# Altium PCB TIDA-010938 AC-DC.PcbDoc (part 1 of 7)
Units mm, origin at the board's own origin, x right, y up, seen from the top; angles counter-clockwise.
Board outline 275 x 170 mm, 4 copper layers (Top Layer, Layer 1, Layer 2, Bottom Layer), stack 1.787 mm thick; 711 components, 426 nets, 2196 pads, 1444 vias.
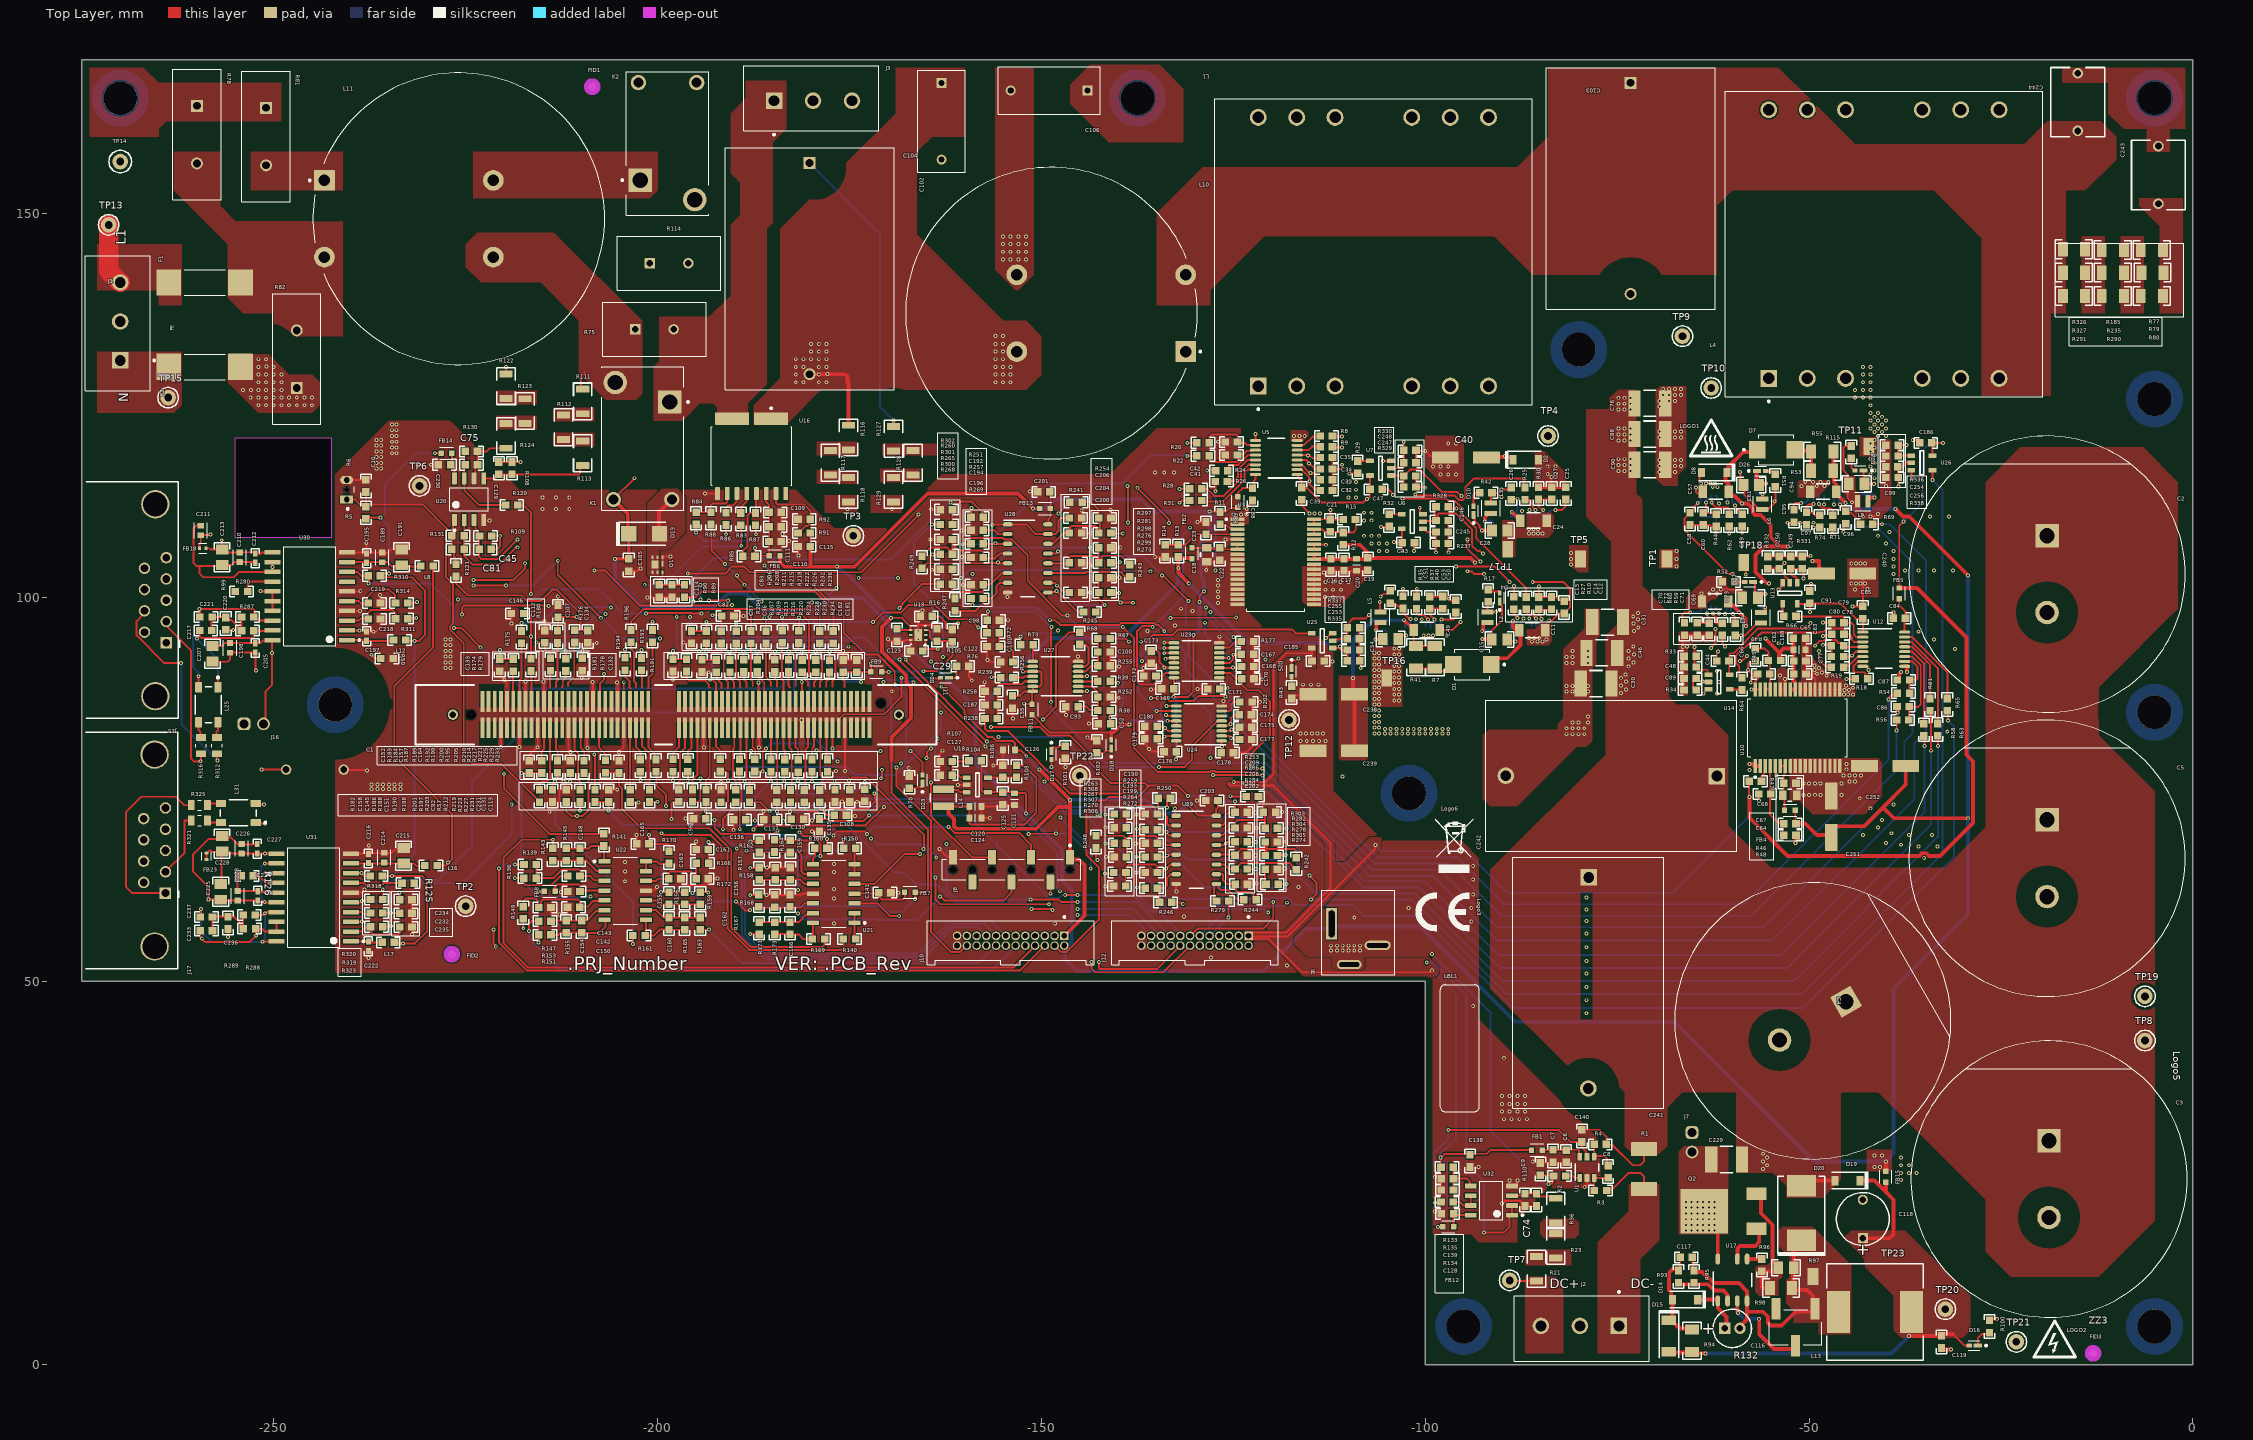
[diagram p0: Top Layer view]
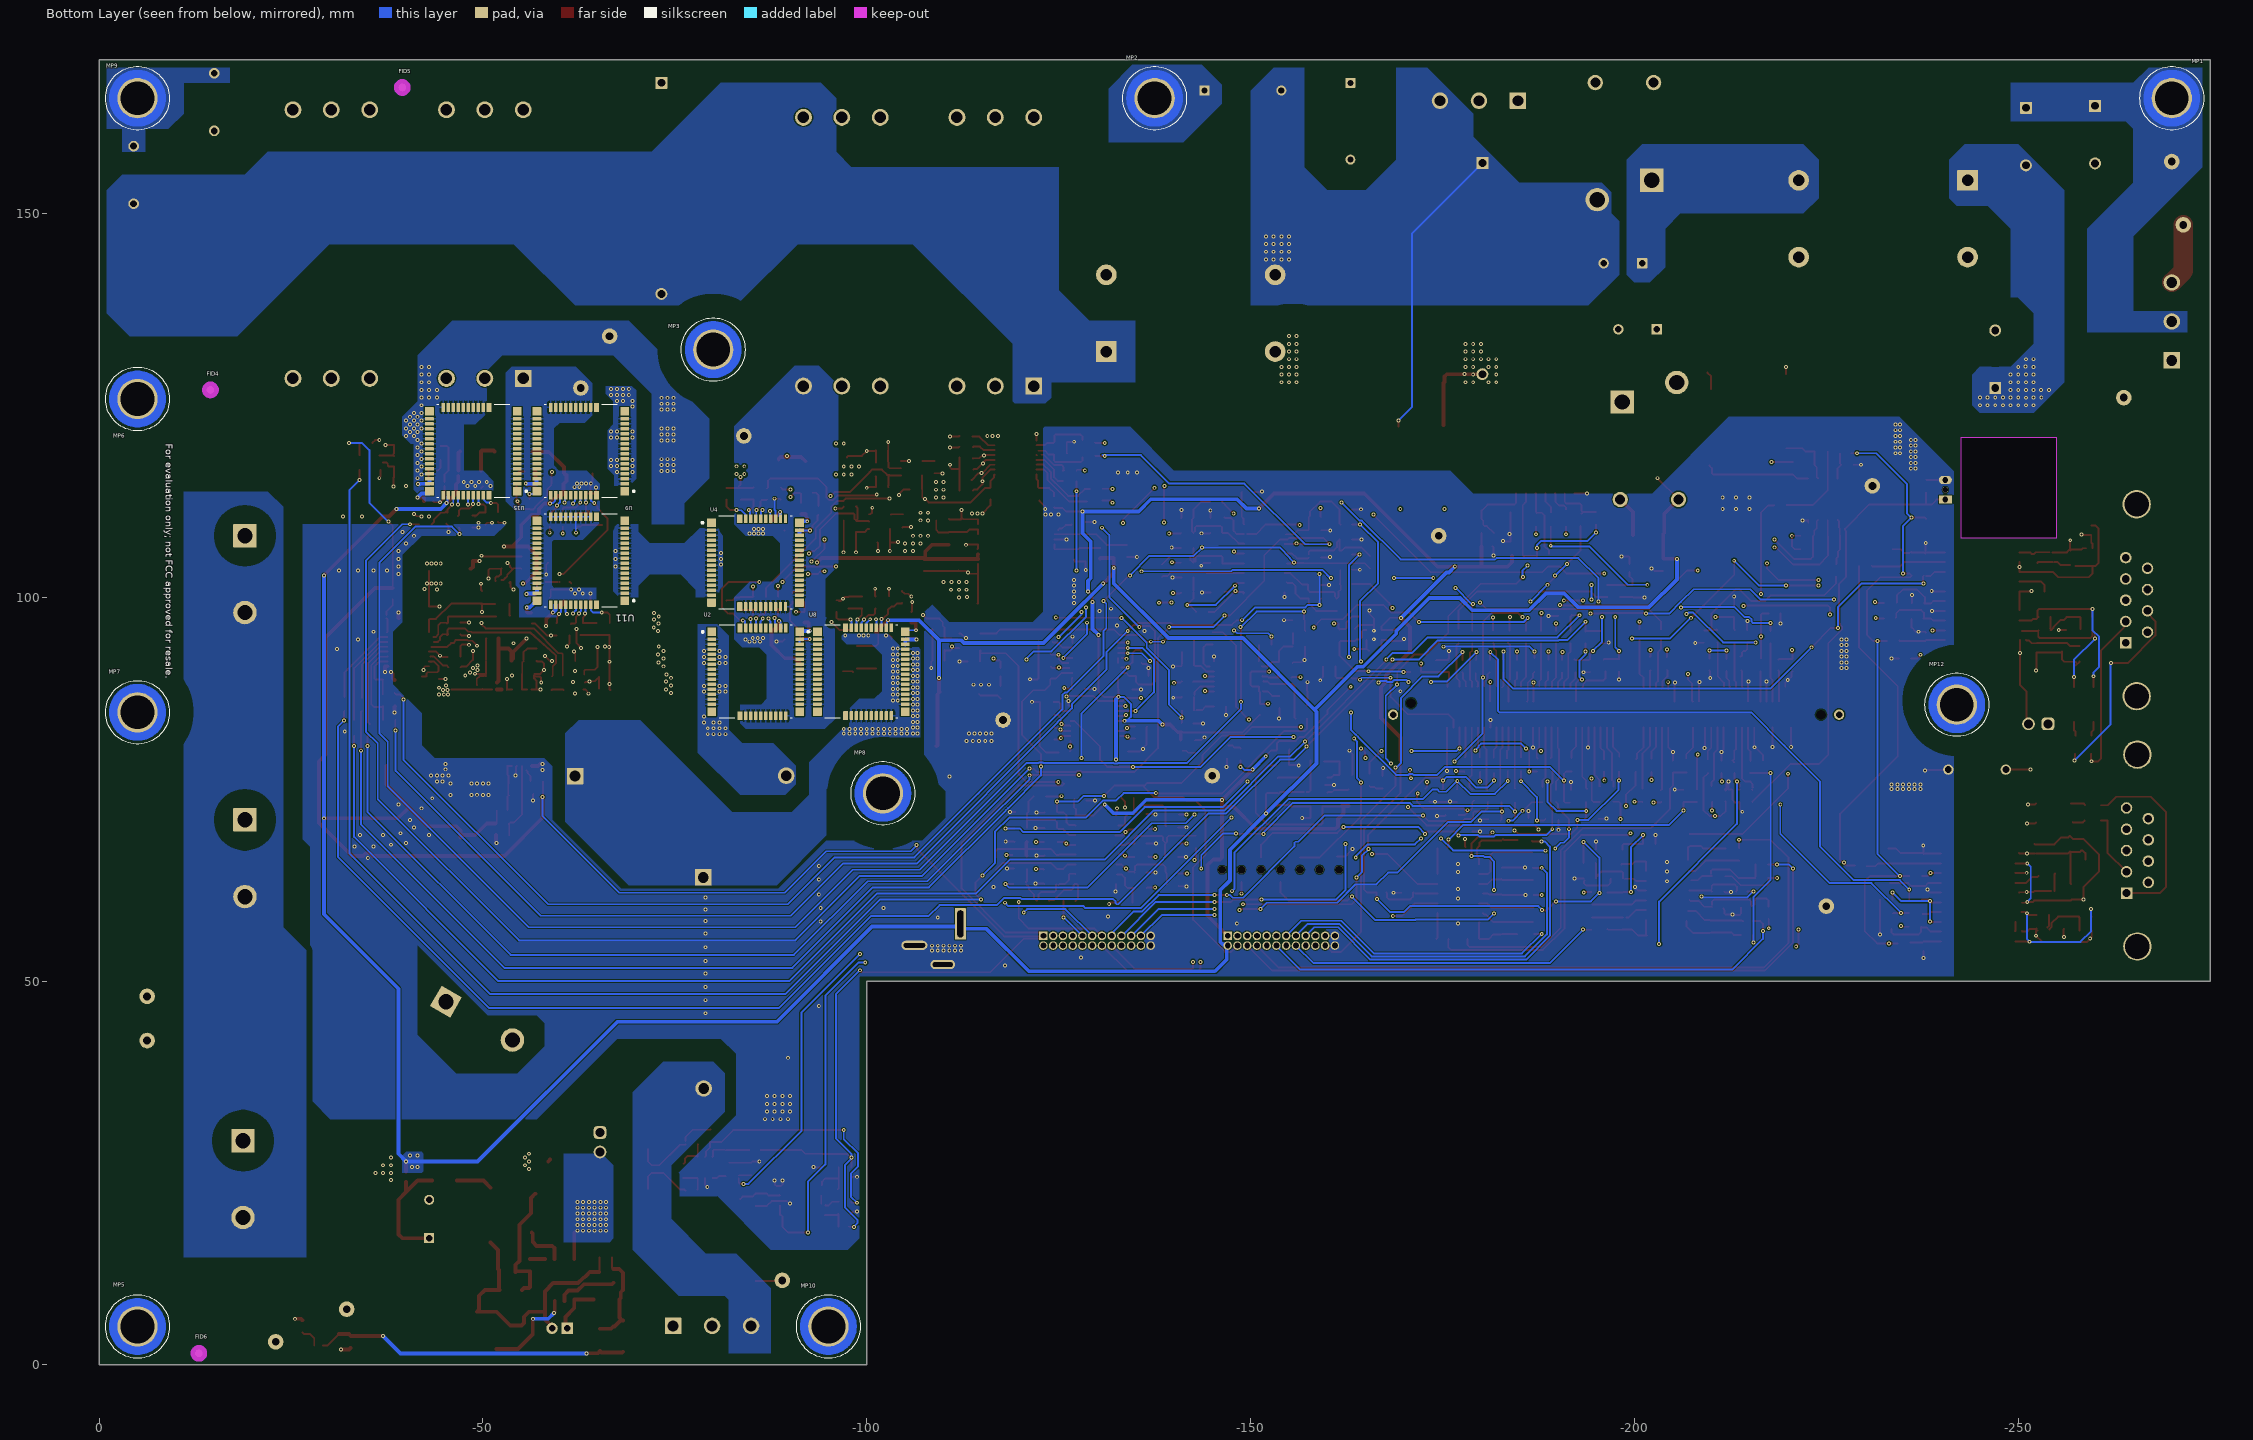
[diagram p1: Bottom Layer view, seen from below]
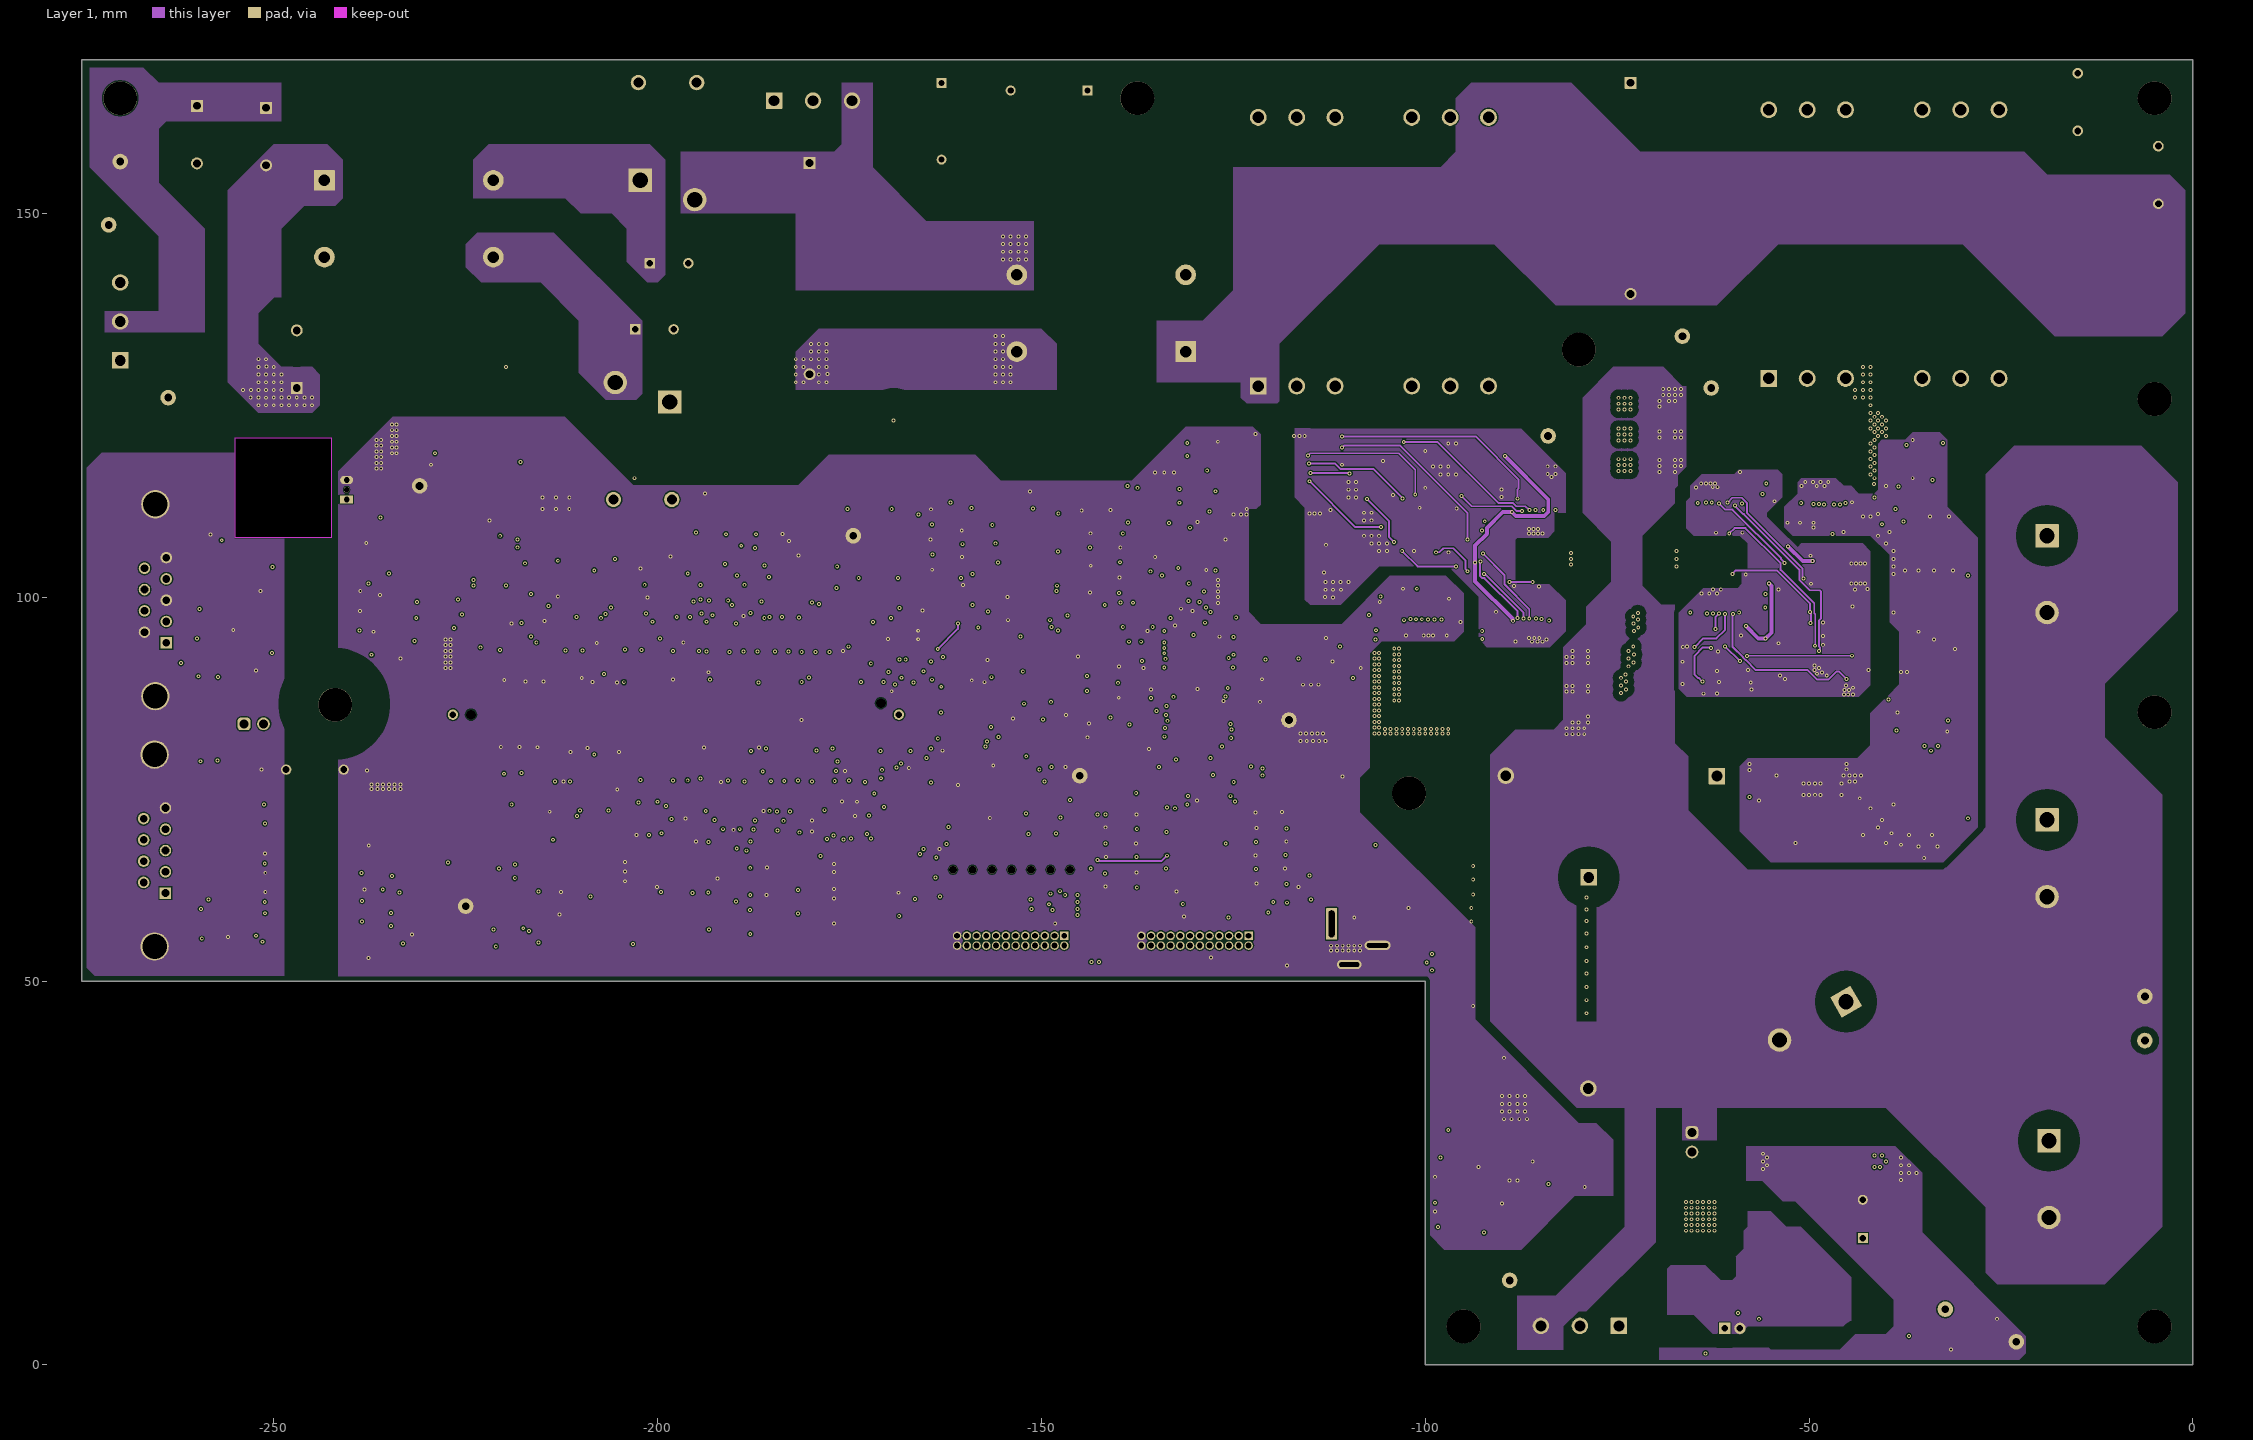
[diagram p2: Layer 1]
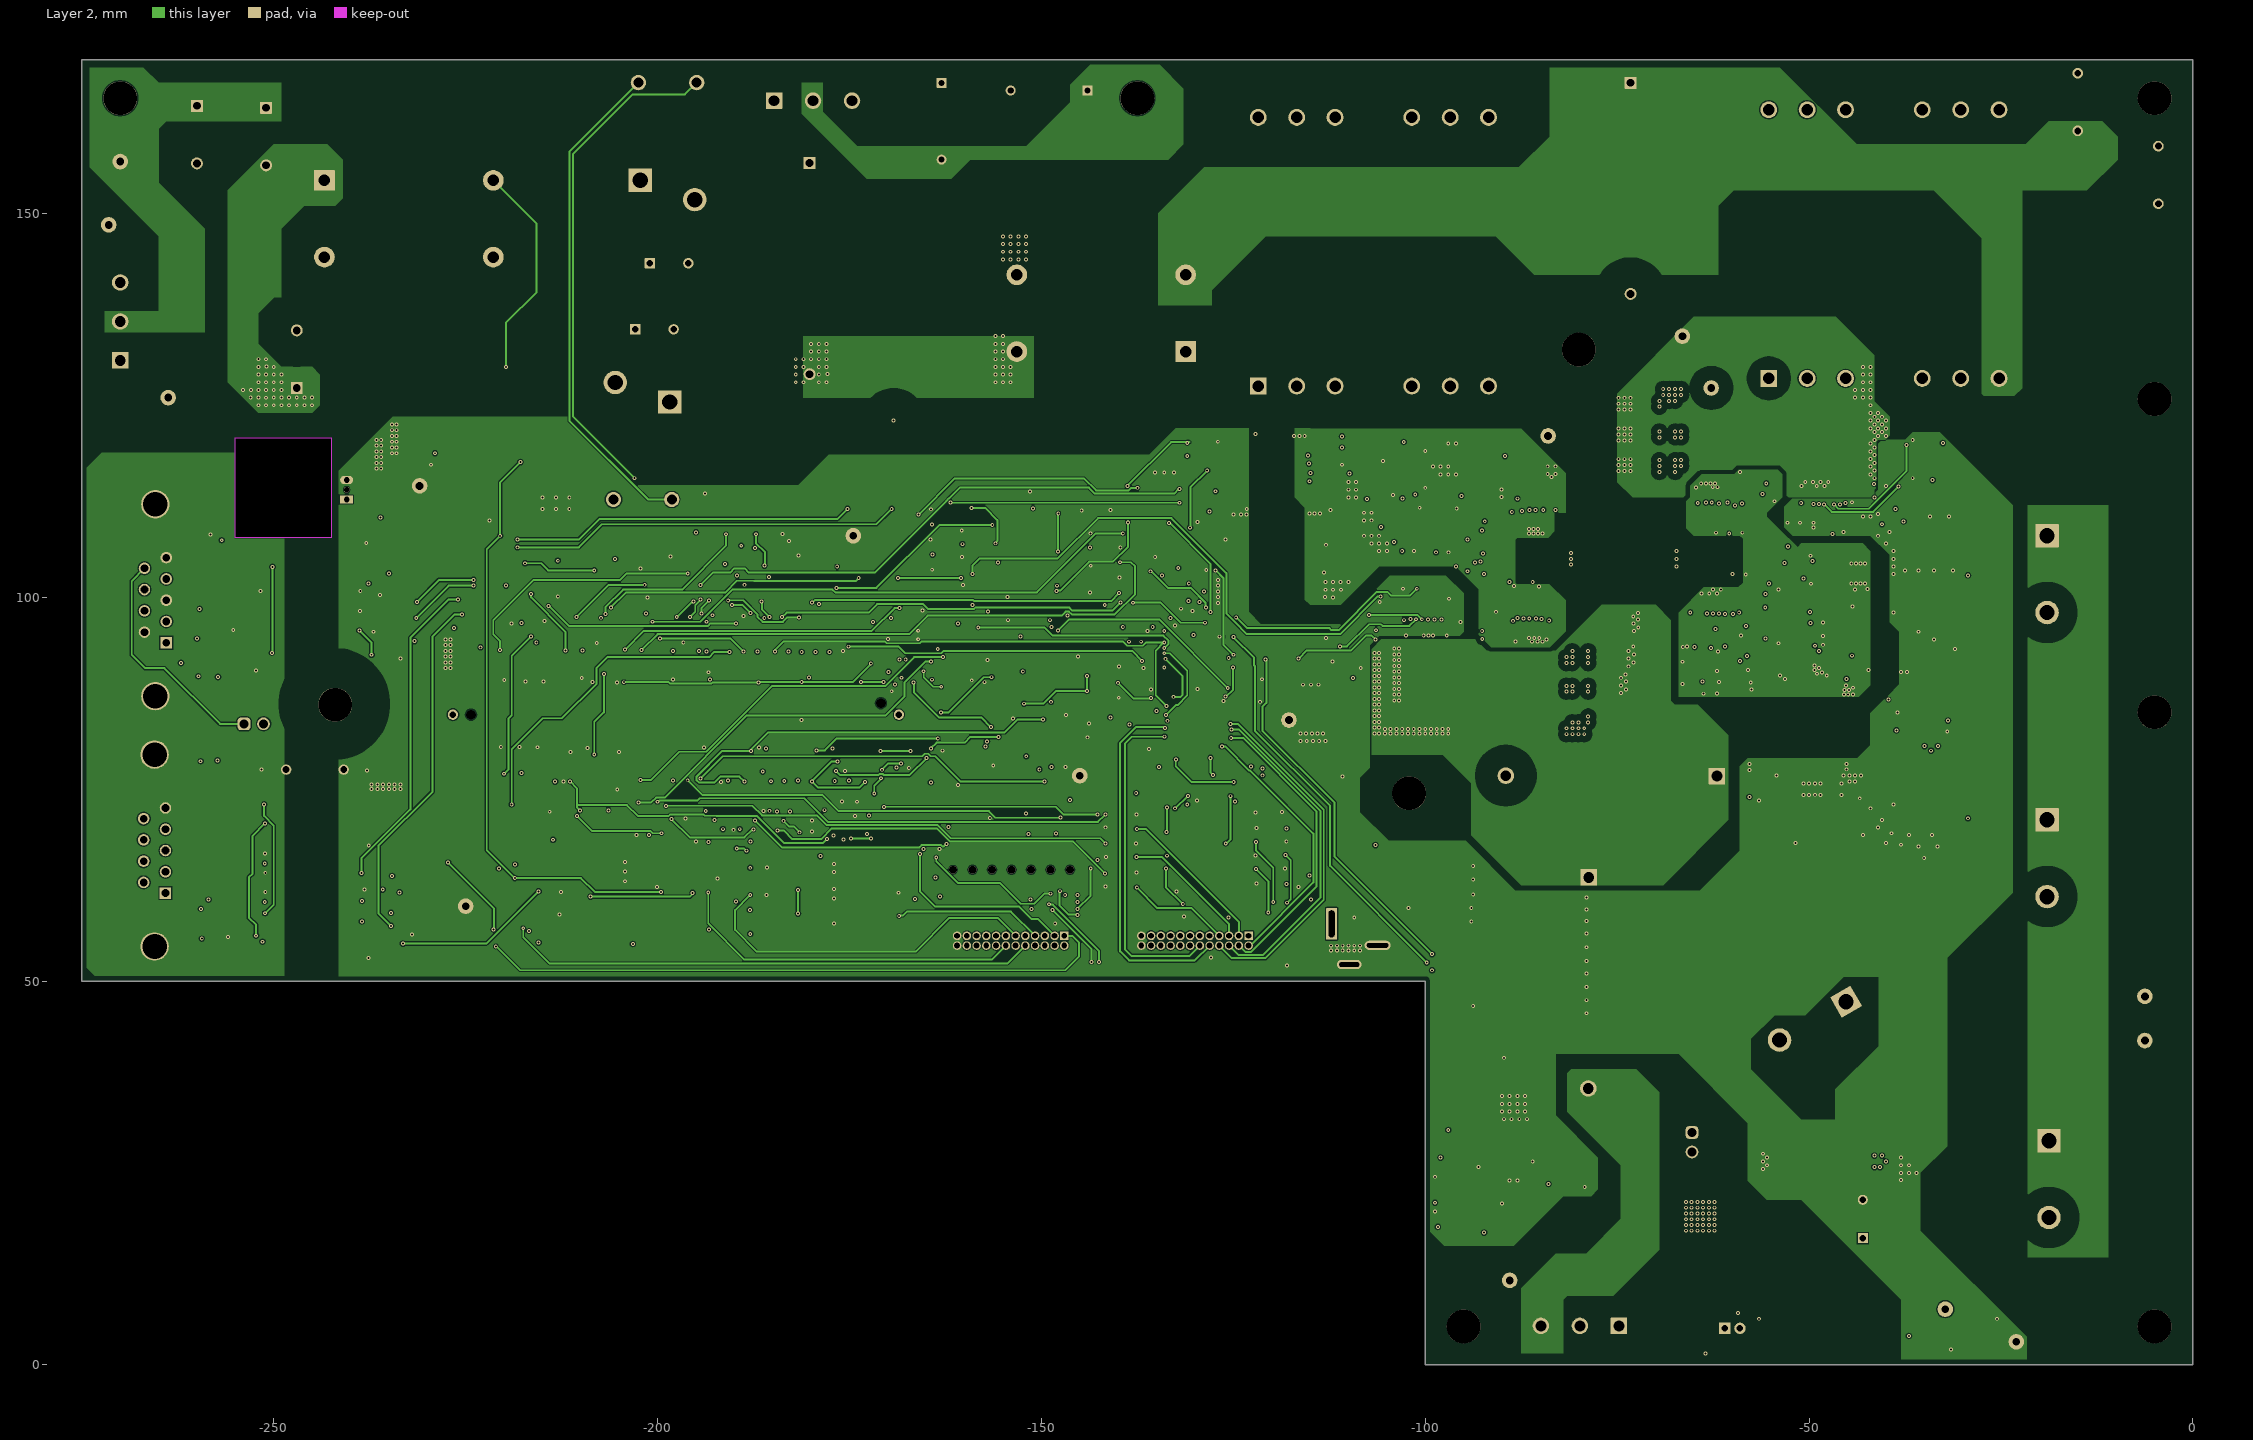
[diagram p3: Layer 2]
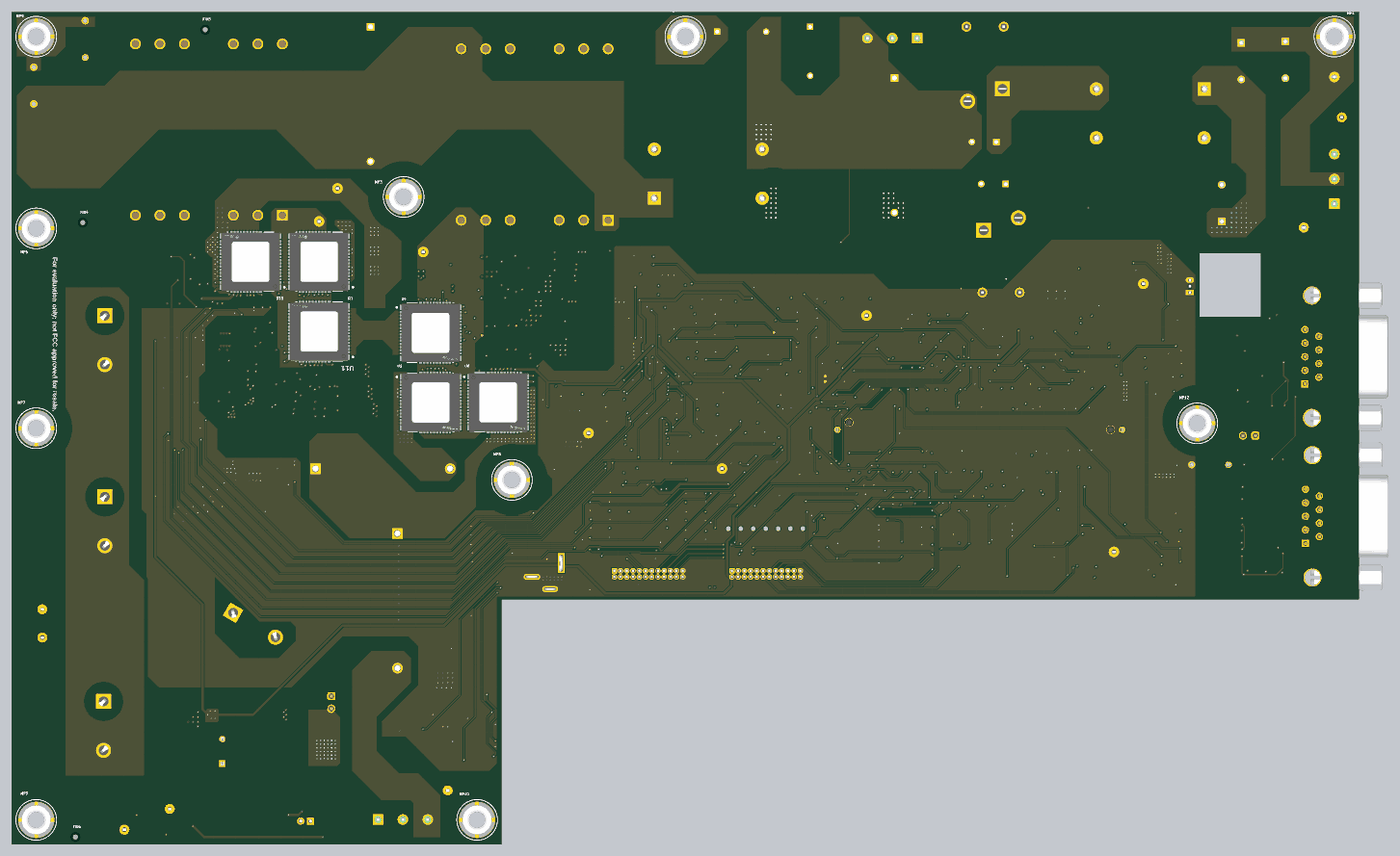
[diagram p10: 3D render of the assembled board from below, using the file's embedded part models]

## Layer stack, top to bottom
Top Solder: solder mask 0.0102, Solder Resist, Dk 3.5
Top Layer: signal copper 0.0356
Dielectric 1: prepreg 0.0711, PP-006, Dk 4.1
Layer 1: signal copper 0.035
Dielectric1: core 1.5037, FR-4 High Tg, Dk 4.8
Layer 2: signal copper 0.035
Dielectric 2: prepreg 0.0711, PP-006, Dk 4.1
Bottom Layer: signal copper 0.0356
Bottom Solder: solder mask 0.0102, Solder Resist, Dk 3.5

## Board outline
-100,0 0,0 0,170 -275,170 -275,50 -100,50
cut-out: -242.5,120.75 -242.5,107.75 -255,107.75 -255,120.75

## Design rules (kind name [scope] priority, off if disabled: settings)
AcuteAngle [All] p1: minimum=4.50000000000000E+0001 checktracksonly=FALSE
AssemblyTestPointUsage [All] p1: valid=2
BoardOutlineClearance BoardOutlineClearance_MountingHoles [OnCopper and InComponentClass('Mounting Holes')] p1: gap=1 ignorepadtopadclearanceinfootprint=FALSE
BoardOutlineClearance BoardOutlineClearance_Poly [OnCopper and IsPoly] p2: gap=0.635 ignorepadtopadclearanceinfootprint=FALSE
BoardOutlineClearance [OnCopper and Not InComponentClass('Logo') and not InComponentClass('FiducialMark') and not InRegion(1000,500,4000,800) and not InPoly] p3: gap=1.016 ignorepadtopadclearanceinfootprint=FALSE
Clearance PE_PELV [InNetClass('PE') vs InNetClass('PELV')] p1: gap=2 ignorepadtopadclearanceinfootprint=FALSE
Clearance BUCK [InNetClass('HVP')   OR InNetClass('HVN') vs InNetClass('Buck')] p2: gap=1.8 ignorepadtopadclearanceinfootprint=FALSE
Clearance SW1 [(InNetClass('HVN')) OR (InNetClass('HVP')) vs InNetClass('HV_SW_Node1')] p3: gap=0.6 ignorepadtopadclearanceinfootprint=FALSE
Clearance SW2 [(InNetClass('HVN')) OR (InNetClass('HVP')) vs InNetClass('HV_SW_Node2')] p4: gap=0.6 ignorepadtopadclearanceinfootprint=FALSE
Clearance SWMID [((InNetClass('HV_SW_Node1')) OR (InNetClass('HV_SW_Node2'))) vs InNetClass('HV_SW_Mid')] p5: gap=2.1 ignorepadtopadclearanceinfootprint=FALSE
Clearance ACL_ACN [InNetClass('ACL') vs InNetClass('ACN')] p6: gap=4 ignorepadtopadclearanceinfootprint=FALSE
Clearance PE [InNetClass('PE') vs InNetClass('All Nets')] p7 off: gap=2.5 ignorepadtopadclearanceinfootprint=FALSE
Clearance PELV [InNetClass('PELV')] p8 off: gap=6 ignorepadtopadclearanceinfootprint=FALSE
Clearance HVN_HVP [InNetClass('HVN') vs InNetClass('HVP')] p9: gap=0.8 ignorepadtopadclearanceinfootprint=FALSE
Clearance Minimum_Distance [All] p10: gap=0.15 ignorepadtopadclearanceinfootprint=FALSE
Clearance Clearance_Keepouts [((IsTrack Or IsArc) And Not InPoly) And IsFree and IsKeepOut vs ((IsTrack Or IsArc) And Not InPoly) And IsFree and IsKeepOut] p11 off: gap=0 ignorepadtopadclearanceinfootprint=FALSE
Clearance Clearance_Poly [InPolygon] p12: gap=0.254 ignorepadtopadclearanceinfootprint=TRUE
Clearance Clearance_FiducialMark [IsKeepOut and InComponentClass('FiducialMark') vs IsPad and InComponentClass('FiducialMark')] p13: gap=0 ignorepadtopadclearanceinfootprint=FALSE
ComponentClearance ComponentClearance_MountingHoles_FiducialMarks [InComponentClass('Mounting Holes') vs InComponentClass('FiducialMark')] p1: gap=1.27 collisioncheckmode=3 verticalgap=0.254 showdistances=FALSE
ComponentClearance ComponentClearance_Shunt [InComponentClass('Header') vs InComponentClass('Shunt')] p2: gap=0 collisioncheckmode=3 verticalgap=0 showdistances=FALSE
ComponentClearance ComponentClearance_Logo [InComponentClass('Logo')] p3: gap=0.762 collisioncheckmode=3 verticalgap=0.254 showdistances=FALSE
ComponentClearance ComponentClearance_ScrewToNut [(HasFootprint('NY PMS 440 0025 PH')) vs (HasFootprint('Keystone_1902C'))] p4: gap=0.127 collisioncheckmode=3 verticalgap=0.254 showdistances=FALSE
ComponentClearance ComponentClearance_MountingHoles [InComponentClass('Mounting Holes')] p5: gap=2.54 collisioncheckmode=3 verticalgap=2540 showdistances=FALSE
ComponentClearance ComponentClearance_SmallPassives [HasFootprint('0201*') or HasFootprint('0402*') or HasFootprint('0508') or HasFootprint('0603*') or HasFootprint('0612') or HasFootprint('0805*') or HasFootprint('0815*') or HasFootprint('0830*') or HasFootprint('1206*') or HasFootprint('1210*') or HasFootprint('1808*') or HasFootprint('1812*') or HasFootprint('1825*') or HasFootprint('2010*') or HasFootprint('2220*') or HasFootprint('2225*') or HasFootprint('2512*') or HasFootprint('2728*') or HasFootprint('3518*') vs HasFootprint('0201*') or HasFootprint('0402*') or HasFootprint('0508') or HasFootprint('0603*') or HasFootprint('0612') or HasFootprint('0805*') or HasFootprint('0815*') or HasFootprint('0830*') or HasFootprint('1206*') or HasFootprint('1210*') or HasFootprint('1808*') or HasFootprint('1812*') or HasFootprint('1825*') or HasFootprint('2010*') or HasFootprint('2220*') or HasFootprint('2225*') or HasFootprint('2512*') or HasFootprint('2728*') or HasFootprint('3518*')] p6: gap=0.38 collisioncheckmode=3 verticalgap=0.254 showdistances=FALSE
ComponentClearance ComponentClearance_THtoSMT [IsThruComponent vs IsSMTComponent] p7: gap=0.762 collisioncheckmode=3 verticalgap=0.762 showdistances=FALSE
ComponentClearance ComponentClearance_THtoTH [IsThruComponent vs IsThruComponent] p8: gap=0.508 collisioncheckmode=3 verticalgap=0.762 showdistances=FALSE
ComponentClearance [All] p9: gap=0.508 collisioncheckmode=3 verticalgap=0.254 showdistances=FALSE
DiffPairsRouting [All] p1: maxlimit=2.54 minlimit=0.254 mostfreqgap=0.254 toplayer_minwidth=0.381 toplayer_maxwidth=0.381 toplayer_prefwidth=0.381 midlayer1_minwidth=0.381 midlayer1_maxwidth=0.381 midlayer1_prefwidth=0.381 midlayer2_minwidth=0.381 midlayer2_maxwidth=0.381 midlayer2_prefwidth=0.381 bottomlayer_minwidth=0.381 bottomlayer_maxwidth=0.381 bottomlayer_prefwidth=0.381 maxuncoupledlength=25.4
FabricationTestPointUsage TestPointUsage [All] p1: valid=2 allowmultiple=FALSE
FabricationTestpoint Testpoint [All] p1: side=3 testpointundercomponent=TRUE minsize=1.016 maxsize=2.54 preferedsize=1.524 minholesize=0 maxholesize=1.016 preferedholesize=0.813 testpointgrid=0.025 allowsidetop=TRUE allowsidebottom=TRUE usegrid=TRUE gridtolerance=0
FanoutControl Fanout_LCC [IsLCC] p1: bgadir=Out bgaviamode=Centered fanoutstyle=Auto fanoutdirection=Alternating viagrid=0.025 // Fanout_LCC (Default Rule)
FanoutControl Fanout_BGA [IsBGA] p2: bgadir=Out bgaviamode=Centered fanoutstyle=Auto fanoutdirection=Alternating viagrid=0.025 // Fanout_BGA (Default Rule)
FanoutControl Fanout_Default [All] p4: bgadir=Out bgaviamode=Centered fanoutstyle=Auto fanoutdirection=Alternating viagrid=0.025 // Fanout_Default (Default Rule)
FanoutControl Fanout_Small [(CompPinCount < 5)] p5: bgadir=Out bgaviamode=Centered fanoutstyle=Auto fanoutdirection=OutThenIn viagrid=0.025 // Fanout_Small (Default Rule)
HoleSize [All] p1: absolutevalues=TRUE maxlimit=6.375 minlimit=0.2 maxpercent=80.000 minpercent=20.000
MinimumAnnularRing MinimumAnnularRing_ThermalPadVias [IsVia and InAnyComponent] p1: minimumring=0.125
MinimumAnnularRing [All] p2: minimumring=0.125
MinimumSolderMaskSliver MinimumSolderMaskSliver_Logo [InComponentClass('Logo') vs InComponentClass('Logo')] p1: minsoldermaskwidth=0.018
MinimumSolderMaskSliver [All] p2: minsoldermaskwidth=0.1
PlaneConnect [All] p1: planeconnectstyle=Relief reliefexpansion=0.254 reliefentries=4 reliefconductorwidth=0.254 reliefairgap=0.254
PolygonConnect "GaN 1" [IsNamedPolygon('Bottom Layer-DC Bus-')] p1: thpad.connectstyle=Direct thpad.reliefconductorwidth=0.254 thpad.reliefentries=4 thpad.polygonreliefangle="90 Angle" thpad.airgapwidth=0.254 smdpad.connectstyle=Relief smdpad.reliefconductorwidth=0.254 smdpad.reliefentries=4 smdpad.polygonreliefangle="90 Angle" smdpad.airgapwidth=0.254 via.connectstyle=Direct via.reliefconductorwidth=0.254 via.reliefentries=4 via.polygonreliefangle="90 Angle" via.airgapwidth=0.254
PolygonConnect "GaN 2" [IsNamedPolygon('BOTTOM_LAYER_SW_2_P000')] p2: thpad.connectstyle=Direct thpad.reliefconductorwidth=0.254 thpad.reliefentries=4 thpad.polygonreliefangle="90 Angle" thpad.airgapwidth=0.254 smdpad.connectstyle=Relief smdpad.reliefconductorwidth=0.254 smdpad.reliefentries=4 smdpad.polygonreliefangle="90 Angle" smdpad.airgapwidth=0.254 via.connectstyle=Direct via.reliefconductorwidth=0.254 via.reliefentries=4 via.polygonreliefangle="90 Angle" via.airgapwidth=0.254
PolygonConnect "GaN 3" [IsNamedPolygon('BOTTOM_LAYER_SW_MID_P059')] p3: thpad.connectstyle=Direct thpad.reliefconductorwidth=0.254 thpad.reliefentries=4 thpad.polygonreliefangle="90 Angle" thpad.airgapwidth=0.254 smdpad.connectstyle=Relief smdpad.reliefconductorwidth=0.254 smdpad.reliefentries=4 smdpad.polygonreliefangle="90 Angle" smdpad.airgapwidth=0.254 via.connectstyle=Direct via.reliefconductorwidth=0.254 via.reliefentries=4 via.polygonreliefangle="90 Angle" via.airgapwidth=0.254
PolygonConnect "GaN 4" [IsNamedPolygon('BOTTOM_LAYER_DC_BUS+_P066')] p4: thpad.connectstyle=Direct thpad.reliefconductorwidth=0.254 thpad.reliefentries=4 thpad.polygonreliefangle="90 Angle" thpad.airgapwidth=0.254 smdpad.connectstyle=Relief smdpad.reliefconductorwidth=0.254 smdpad.reliefentries=4 smdpad.polygonreliefangle="90 Angle" smdpad.airgapwidth=0.254 via.connectstyle=Direct via.reliefconductorwidth=0.254 via.reliefentries=4 via.polygonreliefangle="90 Angle" via.airgapwidth=0.254
PolygonConnect "GaN 5" [IsNamedPolygon('BOTTOM_LAYER_SW_1_P025')] p5: thpad.connectstyle=Direct thpad.reliefconductorwidth=0.254 thpad.reliefentries=4 thpad.polygonreliefangle="90 Angle" thpad.airgapwidth=0.254 smdpad.connectstyle=Relief smdpad.reliefconductorwidth=0.254 smdpad.reliefentries=4 smdpad.polygonreliefangle="90 Angle" smdpad.airgapwidth=0.254 via.connectstyle=Direct via.reliefconductorwidth=0.254 via.reliefentries=4 via.polygonreliefangle="90 Angle" via.airgapwidth=0.254
PolygonConnect "GaN 6" [IsNamedPolygon('BOTTOM_LAYER_DC_BUS+_P007')] p6: thpad.connectstyle=Direct thpad.reliefconductorwidth=0.254 thpad.reliefentries=4 thpad.polygonreliefangle="90 Angle" thpad.airgapwidth=0.254 smdpad.connectstyle=Relief smdpad.reliefconductorwidth=0.254 smdpad.reliefentries=4 smdpad.polygonreliefangle="90 Angle" smdpad.airgapwidth=0.254 via.connectstyle=Direct via.reliefconductorwidth=0.254 via.reliefentries=4 via.polygonreliefangle="90 Angle" via.airgapwidth=0.254
PolygonConnect "GaN 7" [IsNamedPolygon('BOTTOM_LAYER_DC_BUS-_P082')] p7: thpad.connectstyle=Direct thpad.reliefconductorwidth=0.254 thpad.reliefentries=4 thpad.polygonreliefangle="90 Angle" thpad.airgapwidth=0.254 smdpad.connectstyle=Relief smdpad.reliefconductorwidth=0.254 smdpad.reliefentries=4 smdpad.polygonreliefangle="90 Angle" smdpad.airgapwidth=0.254 via.connectstyle=Direct via.reliefconductorwidth=0.254 via.reliefentries=4 via.polygonreliefangle="90 Angle" via.airgapwidth=0.254
PolygonConnect [All] p8: connectstyle=Direct reliefconductorwidth=0.254 reliefentries=4 polygonreliefangle="90 Angle" airgapwidth=0.254
RoutingVias ThermalPadVias [IsVia and InAnyComponent] p1: holewidth=0.254 width=0.508 viastyle="Through Hole" minholewidth=0.2 minwidth=0.5 maxholewidth=1.016 maxwidth=1.651
RoutingVias [All] p2: holewidth=0.254 width=0.508 viastyle="Through Hole" minholewidth=0.2 minwidth=0.5 maxholewidth=1.016 maxwidth=1.651
SilkToBoardRegionClearance [Not ((IsComment or IsDesignator) And (Hide <> 'False')) and not InRegion(1000,500,4000,800)] p1:
SilkToSilkClearance SilkToSilkClearance_Pb-FreeLogo [(HasFootprint('Pb-Free_Overlay_Medium') OR HasFootprint('Pb-Free_Overlay_Small')) vs (HasFootprint('Pb-Free_Overlay_Medium') OR HasFootprint('Pb-Free_Overlay_Small'))] p1: silktosilkclearance=0
SilkToSilkClearance [All] p2: silktosilkclearance=0.1
SilkToSolderMaskClearance SilkToComponentPadClearance [(IsPad or IsFill or IsRegion) and InAnycomponent] p1: minsilkscreentomaskgap=0.127 clearancetoexposedcopper=TRUE
SilkToSolderMaskClearance "Silk to Solder Mask Opening" [All] p2: minsilkscreentomaskgap=0.1 clearancetoexposedcopper=FALSE
SolderMaskExpansion [All] p1: expansion=0.05 istentingtop=FALSE
UnRoutedNet [All] p1: checkbadconnections=TRUE
Width [All] p1: maxlimit=2.54 minlimit=0.25 preferedwidth=0.5 checkconnectedcopper=TRUE
14 further rules are at their usual default settings.

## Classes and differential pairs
net class LOADN: ACLOAD_N
net class LOADL: ACLOAD_L
net class HVP: "DC Bus+" NetC229_1
net class HV_SW_Mid: SW_mid
net class PE: PE PE2 PE3
net class ACN: AC_N ACLOAD_N NetC103_1 NetF2_1 VAC_N
net class ACL: AC_L ACLOAD_L NetC103_2 NetF1_1 VAC_L VAC_SW+
net class Buck: NetC116_1 NetC116_2 NetC117_1 NetQ2_1 NetQ2_3 NetR93_1 NetR96_1 NetR132_2 NetU17_3
net class HVN: 1V65_HVN 1V65_REF 3V3_HVN 5V_HVN 12V_HVN Batt_H1 Batt_H1_Buff Batt_H2 Batt_H2_Buff Batt_L1 Batt_L1_Buff Batt_L2 Batt_L2_Buff Boost_S1 Boost_S1_Buff Boost_S2 Boost_S2_Buff CAN_RX CAN_TX CS_Batt1 CS_Batt1+ CS_Batt1- CS_Batt2 CS_Batt2+ CS_Batt2- CS_Boost1 CS_Boost1+ CS_Boost1- CS_Boost2 CS_Boost2+ CS_Boost2- "DC Bus-" Enable_Buffer_ACDC Enable_Buffer_DCDC Enable_CAN Enable_RS485 F\A\U\L\T\_O\C\_Batt_H1_Buff F\A\U\L\T\_O\C\_Batt_H2_Buff F\A\U\L\T\_O\C\_Batt_L1_Buff F\A\U\L\T\_O\C\_Batt_L2_Buff F\A\U\L\T\_O\C\_Boost1_Buff F\A\U\L\T\_O\C\_Boost2_Buff F\A\U\L\T\_O\C\_S1 F\A\U\L\T\_O\C\_S2 F\A\U\L\T\_O\C\_S2_init F\A\U\L\T\_O\C\_S3 F\A\U\L\T\_O\C\_S4 F\A\U\L\T\_O\C\_S4_init F\A\U\L\T\_O\C\_S5 F\A\U\L\T\_O\C\_S6 F\A\U\L\T\_S2_init F\A\U\L\T\_S4_init IAC_F\A\U\L\T\ IAC_O\C\ IAC_REF IAC_sense IDC_sense NetC6_1 NetC8_1 NetC8_2 NetC18_2 NetC23_2 NetC29_2 NetC38_1 NetC41_2 NetC42_2 NetC45_1 NetC50_2 NetC51_2 NetC53_2 NetC54_1 NetC55_1 NetC64_2 NetC68_2 NetC74_2 NetC75_1 NetC75_2 NetC81_1 NetC81_2 NetC84_1 NetC86_2 NetC87_2 NetC93_2 NetC95_2 NetC96_2 NetC97_2 NetC99_1 NetC100_2 NetC101_2 NetC109_1 NetC114_1 NetC118_1 NetC127_2 NetC128_2 NetC129_1 NetC139_2 NetC141_2 NetC142_2 NetC143_2 NetC148_1 NetC148_2 NetC150_1 NetC154_1 NetC154_2 NetC155_2 NetC156_1 NetC159_1 NetC159_2 NetC160_1 NetC160_2 NetC162_1 NetC163_2 NetC166_1 NetC166_2 NetC181_2 NetC187_2 NetC189_2 NetC190_2 NetC192_2 NetC193_2 NetC194_2 NetC196_2 NetC197_1 NetC199_2 NetC200_2 NetC201_1 NetC202_2 NetC204_2 NetC206_2 NetC208_2 NetC209_2 NetC214_2 NetC218_2 NetC219_2 NetC222_1 NetC230_2 NetC234_2 NetC235_2 NetD1_2 NetD7_2 NetD16_1 NetD17_1 NetD18_1 NetD23_1 NetD23_2 NetD24_1 NetD24_2 NetD25_2 NetD28_2 NetH1_1 NetH2_1 NetH3_1 NetH4_1 NetH9_1 NetH10_1 NetH11_1 NetH12_1 NetJ2_1 NetJ8_2 NetJ8_3 NetJ8_4 NetJ8_5 NetJ10_16 NetJ10_18 NetJ10_20 NetJ10_22 NetJ11_1 NetJ11_2 NetJ11_3 NetJ11_4 NetJ11_5 NetJ11_6 NetJ11_8 NetJ11_9 NetJ11_11 NetJ11_12 NetJ11_14 NetJ11_18 NetJ11_20 NetJ11_21 NetJ11_23 NetJ11_24 NetJ11_25 NetJ11_26 NetJ11_27 NetJ11_28 NetJ11_30 NetJ11_31 NetJ11_32 NetJ11_33 NetJ11_34 NetJ11_36 NetJ11_39 NetJ11_40 NetJ11_41 NetJ11_42 NetJ11_43 NetJ11_44 NetJ11_45 NetJ11_49 NetJ11_50 NetJ11_51 NetJ11_52 NetJ11_53 NetJ11_54 NetJ11_55 NetJ11_56 NetJ11_57 NetJ11_58 NetJ11_59 NetJ11_60 NetJ11_61 NetJ11_62 NetJ11_63 NetJ11_64 NetJ11_66 NetJ11_67 NetJ11_68 NetJ11_69 NetJ11_70 NetJ11_71 NetJ11_72 NetJ11_73 NetJ11_74 NetJ11_75 NetJ11_76 NetJ11_77 NetJ11_78 NetJ11_79 NetJ11_80 NetJ11_81 NetJ11_82 NetJ11_85 NetJ11_86 NetJ11_87 NetJ11_88 NetJ11_89 NetJ11_90 NetJ11_91 NetJ11_92 NetJ11_93 NetJ11_94 NetJ11_95 NetJ11_96 NetJ11_99 NetJ11_100 NetJ11_101 NetJ11_102 NetJ11_103 NetJ11_104 NetJ11_105 NetJ11_106 NetJ11_107 NetJ11_108 NetJ11_109 NetJ11_110 NetJ11_113 NetJ11_114 NetJ11_115 NetJ11_116 NetJ11_117 NetJ11_118 NetJ11_120 NetJ12_20 NetJ12_22 NetJ15_1 NetJ15_8 NetJ17_3 NetJ17_4 NetJ17_6 NetJ17_7 NetJ17_8 NetJ17_9 NetL5_2 NetL9_2 NetL14_1 NetR2_1 NetR11_2 NetR24_2 NetR26_2 NetR28_2 NetR31_2 NetR37_2 NetR39_1 NetR47_2 NetR50_1 NetR58_2 NetR61_2 NetR63_2 NetR65_2 NetR68_1 NetR71_2 NetR73_1 NetR83_1 NetR84_2 NetR85_2 NetR86_2 NetR91_2 NetR103_2 NetR125_1 NetR134_1 NetR140_1 NetR150_1 NetR170_1 NetR177_2 NetR202_2 NetR239_1 NetR240_2 NetR241_2 NetR242_2 NetR243_2 NetR244_2 NetR246_2 NetR247_2 NetR248_2 NetR250_2 NetR251_2 NetR319_2 NetU17_3 NetU19_2 NetU19_5 NetU23_6 NetU24_6 NetU30_2 NetU30_7 NetU30_14 NetU31_7 NetU31_14 O\C\_S2_init O\C\_S4_init PWM_S1 PWM_S1_Buff PWM_S2 PWM_S2_Buff PWM_S3 PWM_S4 PWM_S5 PWM_S5_Buff PWM_S6 PWM_S6_Buff RS485_D RS485_DE_R\E\ RS485_R RY_DCPreCharge RY_PreCharge SN_Relays_PreCharge TEMP_ACDC TEMP_AMB_sense TEMP_Batt_H1_Buff TEMP_Batt_H2_Buff TEMP_Batt_L1_Buff TEMP_Batt_L2_Buff TEMP_Boost1_Buff TEMP_Boost2_Buff TEMP_DCDC TEMP_MUX_A TEMP_MUX_B TEMP_MUX_C TEMP_S1 TEMP_S2 TEMP_S2_init TEMP_S3 TEMP_S4 TEMP_S4_init TEMP_S5 TEMP_S6 VAC_sense VDC_sense Vinv_sense VS_Batt1 VS_Batt1+ VS_Batt1- VS_Boost1 VS_Boost1+ VS_Boost1- VS_Boost2 VS_Boost2+ VS_Boost2-
net class PELV: GND_ISO_COMM NetC210_1 NetC217_1 NetC217_2 NetC221_1 NetC233_1 NetC233_2 NetC237_1 NetJ15_1 NetJ15_2 NetJ15_7 NetJ15_8 NetJ15_9 NetJ17_1 NetJ17_2 NetJ17_3 NetJ17_4 NetJ17_6 NetJ17_7 NetJ17_8 NetJ17_9 NetL25_3 NetL25_4 NetL31_3 NetL31_4 NetR99_2 NetR126_2 NetU30_14 NetU31_14 VIN_PWR_CAN VP_CAN VP_RS485
net class HV_SW_Node1: 5V_SW1 12V_SW1 F\A\U\L\T\_O\C\_S1_init F\A\U\L\T\_O\C\_S5_init F\A\U\L\T\_S1 F\A\U\L\T\_S5 IN_PWM_S1 IN_PWM_S5 NetC14_2 NetC15_1 NetC21_1 NetC25_2 NetC27_2 NetC28_1 NetC32_2 NetC33_2 NetC34_2 NetC35_2 NetD4_2 NetD10_2 NetL2_2 NetL3_2 NetR8_1 NetR9_1 NetU3_32 O\C\_S1 O\C\_S5 SW_1 TEMP_S1_init TEMP_S5_init
net class HV_SW_Node2: 5V_SW2 12V_SW2 F\A\U\L\T\_O\C\_S3_init F\A\U\L\T\_O\C\_S6_init F\A\U\L\T\_S3 F\A\U\L\T\_S6 IN_PWM_S3 IN_PWM_S6 NetC60_2 NetC61_1 NetC66_1 NetC70_2 NetC72_2 NetC73_1 NetC77_2 NetC78_2 NetC79_2 NetC80_2 NetD26_2 NetD27_2 NetJ15_1 NetJ15_8 NetJ17_3 NetJ17_4 NetJ17_6 NetJ17_7 NetJ17_8 NetJ17_9 NetL6_2 NetL7_2 NetR18_1 NetR19_1 NetU3_32 NetU10_32 NetU30_14 NetU31_14 O\C\_S3 O\C\_S6 SW_2 TEMP_S3_init TEMP_S6_init
component class "U_TIDA-010938 AC-DC_Cover Sheet": C1 C2 C3 C4 C5 C6 C7 C8 C9 C10 C241 C242 FB1 J1 J2 J3 J6 R1 R2 R3 R4 R5 R6 U1
component class Header: J7 J16
component class Designator: C11 C12 C13 C14 C15 C16 C17 C18 C19 C20 C21 C22 C23 C24 C25 C26 C27 C28 C30 C31 C32 C33 C34 C35 C36 C37 C38 C39 C40 C41 C42 C43 C46 C47 C49 C50 C51 C52 C53 C54 C185 C238 C239 C245 C246 C247 C248 C253 C255 D1 D2 D4 D10 D25 FB2 FB3 L2 L3 L5 R7 R8 R9 R10 R11 R12 R13 R14 R15 R17 R20 R22 R24 R25 R26 R27 R28 R29 R30 R31 R32 R35 R37 R40 R41 R42 R43 R237 R328 R329 R330 R335 R337 TP1 TP2 TP3 TP4 TP5 TP6 TP11 TP16 TP17 U2 U3 U4 U5 U6 U7 U8 U25
component class Label: LBL1
component class AssemblyNote: ZZ1 ZZ2 ZZ3 ZZ4
component class FiducialMark: FID1 FID2 FID3 FID4 FID5 FID6

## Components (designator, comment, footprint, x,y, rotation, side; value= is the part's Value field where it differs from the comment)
C1 "CK45-B3FD222KYVNA" CK45_1250x600x1650 -244.636,77.54 r0 top value=2200pF
C2 "ALH82D161DD600" FP-ALH82D161DD600_RADIAL-MFG -19,103 r270 top value=160µF
C3 "ALH82D161DD600" FP-ALH82D161DD600_RADIAL-MFG -49.514,44.811 r210 top value=160µF
C4 "ALH82D161DD600" FP-ALH82D161DD600_RADIAL-MFG -18.75,24.2 r270 top value=160µF
C5 "ALH82D161DD600" FP-ALH82D161DD600_RADIAL-MFG -19,66 r270 top value=160µF
C6 "06033C104JAT2A" 0603 -81.65,27.175 r270 top value=0.1uF
C7 "TMK107BJ105KA-T" 0603 -83.35,27.2 r270 top value=1uF
C8 "885012206089" 0603 -76.175,25.175 r90 top value=0.01uF
C9 "GRM188R71H221KA01D" 0603 -85,25.5 r270 top value=220pF
C10 "06033C104JAT2A" 0603 -238,114.5 r90 top value=0.1uF
C11 "TMK316AB7106KLHT" 1206_180 -86.05,95.7 r0 top value=10uF
C12 "GRM188R71C224KA01D" 0603 -81.9,98.675 r90 top value=0.22uF
C13 "GRM188R71H221KA01D" 0603 -88.475,99.25 r270 top value=220pF
C14 "GRM188R71H221KA01D" 0603 -83.55,99.225 r270 top value=220pF
C15 "CGA4J3X7R1E225K125AB" 0805_HV -90.325,94.5 r0 top value=2.2uF
C16 "06033C104JAT2A" 0603 -112.275,104.225 r90 top value=0.1uF
C17 "TMK107BJ105KA-T" 0603 -110.575,104.225 r90 top value=1uF
C18 "GRMJN7R61C206ME05" 0704 -128.475,105.525 r90 top value=20uF
C19 "TMK107BBJ106MA-T" 0603 -107.475,104.325 r90 top value=10uF
C20 "ZRB18AR61E106ME01L" FP-ZRB18AR61E106ME01L_0603-MFG -108.975,104.225 r270 top value=10µF
C21 "GRM1885C1H331JA01D" 0603 -112.375,109.325 r90 top value=330pF
C22 "885012206095" 0603 -126.775,105.625 r270 top value=0.1uF
C23 "885012206089" 0603 -128.55,109 r270 top value=0.01uF
C24 "TMK316AB7106KLHT" 1206_180 -85.9,109.975 r0 top value=10uF
C25 "06033C104JAT2A" 0603 -81.7,113.525 r270 top value=0.1uF
C26 "GRM188R71H221KA01D" 0603 -88.8,113.5 r270 top value=220pF
C27 "GRM188R71H221KA01D" 0603 -83.525,113.525 r270 top value=220pF
C28 "CGA4J3X7R1E225K125AB" 0805_HV -90.3,108.7 r0 top value=2.2uF
C29 "06033C104JAT2A" 0603 -166.25,93 r0 top value=0.1uF
C30 "C1812W104KDRACTU" 1812_254 -77.75,88.75 r0 top value=0.1uF
C31 "C1812W104KDRACTU" 1812_254 -76.25,96.75 r0 top value=0.1uF
C32 "GRM188R71H221KA01D" 0603 -112.875,113.9 r180 top value=220pF
C33 "GRM188R71H221KA01D" 0603 -112.875,115.3 r180 top value=220pF
C34 "GRM188R71H221KA01D" 0603 -112.875,116.7 r180 top value=220pF
C35 "GRM188R71H221KA01D" 0603 -112.875,118.2 r180 top value=220pF
C36 "GRM188R71H221KA01D" 0603 -194.2,91.05 r90 top value=220pF
C37 "GRM188R71H221KA01D" 0603 -197.997,91.126 r90 top value=220pF
C38 "885012206095" 0603 -122.5,113.4 r270 top value=0.1uF
C39 "885012206095" 0603 -116.1,113.5 r270 top value=0.1uF
C40 "UWT1E101MCL1GS" UWT_630x770 -94.7,118.2 r180 top value=100uF
C41 "GRM188R71H221KA01D" 0603 -125.25,118.525 r0 top value=220pF
C42 "GRM188R71H221KA01D" 0603 -125.25,120.225 r0 top value=220pF
C43 "06033C104JAT2A" 0603 -102.2,107.1 r0 top value=0.1uF
C44 "06033C104JAT2A" 0603 -61.225,91.675 r180 top value=0.1uF
C45 "GRM1885C1H561JA01D" 0603 -222.45,106.25 r0 top value=560pF
C46 "C1812W104KDRACTU" 1812_254 -77,92.75 r0 top value=0.1uF
C47 "06033C104JAT2A" 0603 -106.4,114.05 r0 top value=0.1uF
C48 "GRM188R71H221KA01D" 0603 -65.5,90.9 r0 top value=220pF
C49 "TMK316AB7106KLHT" 1206_180 -99.8,95.725 r0 top value=10uF
C50 "06033C104JAT2A" 0603 -96.025,98.8 r270 top value=0.1uF
C51 "GRM188R71H221KA01D" 0603 -102.9,99.325 r270 top value=220pF
C52 "GRM188R71H221KA01D" 0603 -141.775,83.525 r0 top value=220pF
C53 "GRM188R71H221KA01D" 0603 -97.7,99.3 r270 top value=220pF
C54 "CGA4J3X7R1E225K125AB" 0805_HV -104.525,94.55 r0 top value=2.2uF
C55 "885012206095" 0603 -153.76,86.343 r270 top value=0.1uF
C56 "GRM188R71H221KA01D" 0603 -194.516,71.134 r0 top value=220pF
C57 "TMK316AB7106KLHT" 1206_180 -62.175,113.75 r180 top value=10uF
C58 "GRM188R71C224KA01D" 0603 -65.5,110.2 r270 top value=0.22uF
C59 "GRM188R71H221KA01D" 0603 -58.7,110 r90 top value=220pF
C60 "GRM188R71H221KA01D" 0603 -63.8,110.2 r90 top value=220pF
C61 "CGA4J3X7R1E225K125AB" 0805_HV -57.525,114.625 r180 top value=2.2uF
C62 "06033C104JAT2A" 0603 -51.2,90 r180 top value=0.1uF
C63 "TMK107BJ105KA-T" 0603 -51.2,91.7 r180 top value=1uF
C64 "GRMJN7R61C206ME05" 0704 -52.525,74.2 r180 top value=20uF
C65 "ZRB18AR61E106ME01L" FP-ZRB18AR61E106ME01L_0603-MFG -51.25,93.15 r0 top value=10µF
C66 "GRM1885C1H331JA01D" 0603 -55.925,90 r180 top value=330pF
C67 "885012206095" 0603 -52.5,75.75 r0 top value=0.1uF
C68 "885012206089" 0603 -55.775,74.35 r0 top value=0.01uF
C69 "TMK316AB7106KLHT" 1206_180 -62.25,99.45 r180 top value=10uF
C70 "GRM188R71C104KA01D" 0603 -66.225,95.85 r90 top value=0.1uF
C71 "GRM188R71H221KA01D" 0603 -59.6,95.8 r90 top value=220pF
C72 "GRM188R71H221KA01D" 0603 -64.575,95.85 r90 top value=220pF
C73 "CGA4J3X7R1E225K125AB" 0805_HV -57.675,99.925 r180 top value=2.2uF
C74 "GRM1885C1H561JA01D" 0603 -87,21.5 r90 top value=560pF
C75 "GRM1885C1H561JA01D" 0603 -224.25,119 r180 top value=560pF
C76 "C1812W104KDRACTU" 1812_254 -70.75,125.25 r180 top value=0.1uF
C77 "GRM188R71H221KA01D" 0603 -46.3,92.275 r0 top value=220pF
C78 "GRM188R71H221KA01D" 0603 -46.3,93.675 r0 top value=220pF
C79 "GRM188R71H221KA01D" 0603 -46.25,95.175 r0 top value=220pF
C80 "GRM188R71H221KA01D" 0603 -46.25,96.675 r0 top value=220pF
C81 "GRM1885C1H561JA01D" 0603 -226,106.25 r180 top value=560pF
C82 "GRM188R71H221KA01D" 0603 -190.85,97.55 r180 top value=220pF
C83 "GRM188R71H221KA01D" 0603 -195.582,94.798 r90 top value=220pF
C84 "885012206095" 0603 -38.25,97.25 r180 top value=0.1uF
C85 "885012206095" 0603 -43,98 r90 top value=0.1uF
C86 "GRM188R71H221KA01D" 0603 -37.75,85.75 r0 top value=220pF
C87 "GRM188R71H221KA01D" 0603 -37.7,89.2 r0 top value=220pF
C88 "C1812W104KDRACTU" 1812_254 -70.75,121.25 r180 top value=0.1uF
C89 "GRM188R71H221KA01D" 0603 -65.5,89.4 r0 top value=220pF
C90 "C1812W104KDRACTU" 1812_254 -70.75,117.25 r180 top value=0.1uF
C91 "06033C104JAT2A" 0603 -49.9,100 r90 top value=0.1uF
C92 "GRM188R71H221KA01D" 0603 -191.75,74.1 r270 top value=220pF
C93 "GRM188R71H221KA01D" 0603 -146.01,85.738 r0 top value=220pF
C94 "TMK316AB7106KLHT" 1206_180 -48.175,113.75 r180 top value=10uF
C95 "GRM188R71C104KA01D" 0603 -51.975,110.575 r90 top value=0.1uF
C96 "GRM188R71H221KA01D" 0603 -45.225,110.375 r90 top value=220pF
C97 "GRM188R71H221KA01D" 0603 -50.325,110.25 r90 top value=220pF
C98 "GRM188R71H221KA01D" 0603 -156.25,97 r180 top value=220pF
C99 "CGA4J3X7R1E225K125AB" 0805_HV -43.8,114.775 r180 top value=2.2uF
C100 "GRM188R71H221KA01D" 0603 -141.846,92.85 r180 top value=220pF
C101 "GRM188R71H221KA01D" 0603 -156.287,93.587 r0 top value=220pF
C102 "R413F168050T0K" FP-R413F168050T0K_RADIAL-MFG -163,162 r270 top value=6.8nF
C103 "F862FY475K310ZV054" FP-F862FY475K310ZV054_RADIAL-MFG -73.25,153.25 r270 top value=4.7µF
C104 "F862FY475K310ZV054" FP-F862FY475K310ZV054_RADIAL-MFG -180.2,142.8 r270 top value=4.7µF
C105 "GRM188R72A104KA35J" 0603 -203.75,104.2 r270 top value=0.1uF
C106 "R413F168050T0K" FP-R413F168050T0K_RADIAL-MFG -149,166 r180 top value=6.8nF
C107 "GRM188R71H221KA01D" 0603 -212.975,98.175 r270 top value=220pF
C108 "GRM188R71H221KA01D" 0603 -176.2,71.6 r180 top value=220pF
C109 "GRM188R72A104KA35J" 0603 -184.677,111.051 r0 top value=0.1uF
C110 "885012206089" 0603 -184.675,109.175 r0 top value=0.01uF
C111 "TMK107BJ105KA-T" 0603 -184.69,107.263 r0 top value=1uF
C112 "GRM188R71H221KA01D" 0603 -214.698,94.872 r270 top value=220pF
C113 "GRM188R71H221KA01D" 0603 -173,74.2 r90 top value=220pF
C114 "885012206095" 0603 -199.775,100.8 r270 top value=0.1uF
C115 "GRM188R72A104KA35J" 0603 -180.896,106.595 r180 top value=0.1uF
C116 "UVR1V100MDD1TA" CAPPR2-5x11 -60,4.75 r0 top value=10uF
C117 "06035A220JAT2A" 0603 -66,14 r0 top value=22pF
C118 "EEU-FR1E151B" FR_630X1120 -43,19 r90 top value=150uF
C119 "TMK107BJ105KA-T" 0603 -32.75,3 r270 top value=1uF
C120 "ZRB18AR61E106ME01L" FP-ZRB18AR61E106ME01L_0603-MFG -158.587,72.755 r0 top value=10µF
C121 "ZRB18AR61E106ME01L" FP-ZRB18AR61E106ME01L_0603-MFG -153.5,73.7 r270 top value=10µF
C122 "885012206026" 0603 -163.596,95.076 r90 top value=1uF
C123 "885012206026" 0603 -168.8,95.075 r270 top value=1uF
C124 "ZRB18AR61E106ME01L" FP-ZRB18AR61E106ME01L_0603-MFG -158.587,71.231 r0 top value=10µF
C125 "06033C104JAT2A" 0603 -155.03,73.771 r90 top value=0.1uF
C126 "ZRB18AR61E106ME01L" FP-ZRB18AR61E106ME01L_0603-MFG -154.23,80.121 r180 top value=10µF
C127 "06033C104JAT2A" 0603 -162.397,76.819 r0 top value=0.1uF
C128 "C0603X104K3RACTU" 0603 -97.1,19.675 r0 top value=0.1uF
C129 "GRM1885C1H561JA01D" 0603 -220.675,116.8 r90 top value=560pF
C130 "GRM188R71H221KA01D" 0603 -181.775,71.075 r180 top value=220pF
C131 "GRM188R71H221KA01D" 0603 -174.975,74.125 r90 top value=220pF
C132 "GRM188R71H221KA01D" 0603 -209.8,91.225 r90 top value=220pF
C133 "GRM188R71H221KA01D" 0603 -220.565,91.139 r90 top value=220pF
C134 "GRM188R71H221KA01D" 0603 -209.099,94.87 r90 top value=220pF
C135 "GRM188R71H221KA01D" 0603 -178.9,70.3 r90 top value=220pF
C136 "GRM188R71H221KA01D" 0603 -189.3,71 r0 top value=220pF
C137 "GRM188R71H221KA01D" 0603 -185.375,71.025 r0 top value=220pF
C138 "C0603X104K3RACTU" 0603 -94.175,26.575 r90 top value=0.1uF
C139 "GRM188R71H221KA01D" 0603 -97.125,22.775 r0 top value=220pF
C140 "C0603X104K3RACTU" 0603 -79.6,29.825 r270 top value=0.1uF
C141 "C0603X104K3RACTU" 0603 -170.395,61.512 r180 top value=0.1uF
C142 "C0603X104K3RACTU" 0603 -210.896,61.65 r0 top value=0.1uF
C143 "GRM1885C1H201JA01D" 0603 -210.896,63.682 r0 top value=200pF
C145 "GRM188R71H221KA01D" 0603 -211.896,74.129 r270 top value=220pF
C146 "GRM188R71H221KA01D" 0603 -218.25,97.875 r0 top value=220pF
C148 "GRM1885C1H201JA01D" 0603 -210.101,66.476 r90 top value=200pF
C150 "GRM1885C1H202JA01D" 0603 -210.934,59.618 r180 top value=2000pF
C151 "GRM188R71H221KA01D" 0603 -206.375,74.116 r270 top value=220pF
C152 "GRM188R71H221KA01D" 0603 -216.725,77.9 r270 top value=220pF
C154 "GRM1885C1H202JA01D" 0603 -209.88,57.078 r270 top value=2000pF
C155 "GRM1885C1H201JA01D" 0603 -198.499,60.78 r270 top value=200pF
C156 "GRM1885C1H202JA01D" 0603 -182.705,63.981 r90 top value=2000pF
C157 "GRM188R71H221KA01D" 0603 -211.363,77.901 r270 top value=220pF
C158 "GRM188R71H221KA01D" 0603 -213.675,74.125 r90 top value=220pF
C159 "GRM1885C1H202JA01D" 0603 -182.705,67.537 r90 top value=2000pF
C160 "GRM1885C1H201JA01D" 0603 -198.499,57.478 r270 top value=200pF
C161 "C0603X104K3RACTU" 0603 -194.181,67.13 r0 top value=0.1uF
C162 "GRM1885C1H202JA01D" 0603 -182.738,60.467 r90 top value=2000pF
C163 "GRM188R71H221KA01D" 0603 -197.737,63.32 r180 top value=220pF
C164 "GRM188R71H221KA01D" 0603 -205.013,77.901 r270 top value=220pF
C165 "C0603X104K3RACTU" 0603 -201.918,67.871 r0 top value=0.1uF
C166 "GRM1885C1H202JA01D" 0603 -182.738,56.873 r270 top value=2000pF
C167 "GRM188R71H221KA01D" 0603 -123.15,92.575 r180 top value=220pF
C168 "GRM188R71H221KA01D" 0603 -123.125,90.975 r180 top value=220pF
C169 "885012206095" 0603 -133.55,88.075 r180 top value=0.1uF
C170 "GRM188R71H221KA01D" 0603 -123.1,89.375 r180 top value=220pF
C171 "GRM188R71H221KA01D" 0603 -127.55,88.05 r0 top value=220pF
C172 "GRM188R71H221KA01D" 0603 -135.875,89.725 r0 top value=220pF
C173 "GRM188R71H221KA01D" 0603 -135.7,92.2 r90 top value=220pF
C174 "GRM188R71H221KA01D" 0603 -123.425,84.675 r180 top value=220pF
C175 "GRM188R71H221KA01D" 0603 -123.4,83.075 r180 top value=220pF
C176 "885012206095" 0603 -133.225,79.875 r180 top value=0.1uF
C177 "GRM188R71H221KA01D" 0603 -123.4,81.45 r180 top value=220pF
C178 "GRM188R71H221KA01D" 0603 -125.775,79.75 r180 top value=220pF
C179 "GRM188R71H221KA01D" 0603 -135.725,81.575 r0 top value=220pF
C180 "GRM188R71H221KA01D" 0603 -135.725,83.175 r0 top value=220pF
C181 "TMK107BJ105KA-T" 0603 -174.05,91.026 r270 top value=1uF
C182 "885012206095" 0603 -175.828,91.026 r90 top value=0.1uF
C185 "06033C104JAT2A" 0603 -113.95,91.675 r0 top value=0.1uF
C186 "06033C104JAT2A" 0603 -34.8,120.1 r180 top value=0.1uF
C187 "GRM188R71H221KA01D" 0603 -156.541,85.967 r0 top value=220pF
C188 "TMK107BBJ106MA-T" 0603 -51.25,94.65 r180 top value=10uF
C189 "CL10A105KA8NNNC" FP-CL10A105KA8NNNC_0603-IPC_C -235.873,105.19 r270 top value=1µF
C190 "GRM188R71H221KA01D" 0603 -135.667,71.747 r0 top value=220pF
C191 "GRM21BR6YA106KE43L" 0805_HV -233.333,105.19 r90 top value=10uF
C192 "GRM188R71H221KA01D" 0603 -158.375,108.725 r0 top value=220pF
C193 "GRM188R71H221KA01D" 0603 -135.667,67.937 r0 top value=220pF
C194 "GRM188R71H221KA01D" 0603 -158.375,105.169 r0 top value=220pF
C195 "CL05B104KO5NNNC" 0402 -237.916,105.08 r90 top value=0.1uF
C196 "GRM188R71H221KA01D" 0603 -158.375,101.613 r0 top value=220pF
C197 "CL05B104KO5NNNC" 0402 -237.916,94.92 r90 top value=0.1uF
C198 "CL10A105KA8NNNC" FP-CL10A105KA8NNNC_0603-IPC_C -255.696,93.396 r90 top value=1µF
C199 "GRM188R71H221KA01D" 0603 -135.667,64.127 r0 top value=220pF
C200 "GRM188R71H221KA01D" 0603 -145.553,100.604 r180 top value=220pF
C201 "885012206095" 0603 -149.7,113.723 r180 top value=0.1uF
C202 "GRM188R71H221KA01D" 0603 -123.945,62.618 r180 top value=220pF
C203 "885012206095" 0603 -127.793,73.504 r180 top value=0.1uF
C204 "GRM188R71H221KA01D" 0603 -145.553,104.487 r180 top value=220pF
C205 "CL05B104KO5NNNC" 0402 -252.394,93.396 r270 top value=0.1uF
C206 "GRM188R71H221KA01D" 0603 -145.553,108.37 r180 top value=220pF
C207 "GRM21BR6YA106KE43L" 0805_HV -257.982,92.634 r270 top value=10uF
C208 "GRM188R71H221KA01D" 0603 -123.983,66.38 r180 top value=220pF
C209 "GRM188R71H221KA01D" 0603 -123.983,69.936 r180 top value=220pF
C210 "CL10A105KA8NNNC" FP-CL10A105KA8NNNC_0603-IPC_C -254.437,105.199 r270 top value=1µF
C211 "CL10A105KA8NNNC" FP-CL10A105KA8NNNC_0603-IPC_C -259.506,108.685 r90 top value=1µF
C212 "0402B103K500CT" 0402 -252.394,105.08 r90 top value=0.01uF
C213 "GRM21BR6YA106KE43L" 0805_HV -256.723,105.199 r90 top value=10uF
C214 "CL10A105KA8NNNC" FP-CL10A105KA8NNNC_0603-IPC_C -235.615,66.074 r270 top value=1µF
C215 "GRM21BR6YA106KE43L" 0805_HV -233.075,66.328 r90 top value=10uF
C216 "CL05B104KO5NNNC" 0402 -237.658,65.964 r90 top value=0.1uF
C217 "GRM1885C1H470JA01D" 0603 -258.857,95.649 r180 top value=47pF
C218 "GRM188R71H221KA01D" 0603 -236.9,97.169 r180 top value=220pF
C219 "GRM188R71H221KA01D" 0603 -236.9,99.234 r180 top value=220pF
C220 "C0603X472K5RACTU" 0603 -256.247,96.549 r90 top value=4700pF
C221 "GRM1885C1H470JA01D" 0603 -258.819,97.427 r0 top value=47pF
C222 "CL05B104KO5NNNC" 0402 -237.658,54.534 r270 top value=0.1uF
C223 "CL10A105KA8NNNC" FP-CL10A105KA8NNNC_0603-IPC_C -254.7,61.1 r270 top value=1µF
C224 "CL05B104KO5NNNC" 0402 -252.1,61.1 r90 top value=0.1uF
C225 "GRM21BR6YA106KE43L" 0805_HV -256.9,61.616 r90 top value=10uF
C226 "CL10A105KA8NNNC" FP-CL10A105KA8NNNC_0603-IPC_C -254.179,67.234 r90 top value=1µF
C227 "0402B103K500CT" 0402 -252.136,67.234 r270 top value=0.01uF
C228 "GRM21BR6YA106KE43L" 0805_HV -256.719,67.877 r270 top value=10uF
C229 "C1812W104KDRACTU" 1812_254 -60.75,26.75 r0 top value=0.1uF
C230 "C0603X104K3RACTU" 0603 -227.75,117.25 r0 top value=0.1uF
C231 "GRM188R71H221KA01D" 0603 -176.9,74.125 r90 top value=220pF
C232 "GRM188R71H221KA01D" 0603 -232.79,58.819 r180 top value=220pF
C233 "GRM1885C1H470JA01D" 0603 -258.778,56.566 r180 top value=47pF
C234 "GRM188R71H221KA01D" 0603 -232.79,60.597 r180 top value=220pF
C235 "GRM188R71H221KA01D" 0603 -232.79,57.041 r180 top value=220pF
C236 "C0603X472K5RACTU" 0603 -255.946,57.582 r90 top value=4700pF
C237 "GRM1885C1H470JA01D" 0603 -258.778,58.344 r0 top value=47pF
C238 "UWT1E101MCL1GS" UWT_630x770 -111.9,87.35 r180 top value=100uF
C239 "UWT1E101MCL1GS" UWT_630x770 -111.9,80 r180 top value=100uF
C240 "UWT1E101MCL1GS" UWT_630x770 -45.7,103.1 r0 top value=100uF
C241 "C4AKOBU4500A31J" FP-C4AKOBU4500A31J_RADIAL-MFG -78.75,49.75 r270 top value=5µF
C242 "C4AKOBU4500A31J" FP-C4AKOBU4500A31J_RADIAL-MFG -75.75,76.75 r180 top value=5µF
C243 "DE6E3KJ222MN3A" E_900x700x900 -4.5,155 r270 top value=2200pF
C244 "DE6E3KJ222MN3A" E_900x700x900 -15,164.5 r90 top value=2200pF
C245 "GRM188R71H221KA01D" 0603 -97.8,108.5 r180 top value=220pF
C246 "GRM188R71H221KA01D" 0603 -97.8,110 r180 top value=220pF
C247 "GRM188R71H221KA01D" 0603 -102.017,115.798 r180 top value=220pF
C248 "GRM188R71H221KA01D" 0603 -102,117.525 r180 top value=220pF
C249 "GRM188R71H221KA01D" 0603 -52.4,104.5 r270 top value=220pF
C250 "GRM188R71H221KA01D" 0603 -53.9,104.5 r270 top value=220pF
C251 "UWT1E101MCL1GS" UWT_630x770 -47.1,71.4 r90 top value=100uF
C252 "UWT1E101MCL1GS" UWT_630x770 -40.1,78 r180 top value=100uF
C253 "GRM188R71H221KA01D" 0603 -109.35,93.125 r180 top value=220pF
C254 "GRM188R71H221KA01D" 0603 -39.2,118.4 r0 top value=220pF
C255 "GRM188R71H221KA01D" 0603 -109.362,94.604 r180 top value=220pF
C256 "GRM188R71H221KA01D" 0603 -39.229,117.008 r0 top value=220pF
D1 "GB02SLT12-214" FP-GB02SLT12-214_DO-214AA-MFG -93.875,91.225 r180 top
D2 "BZT52C16-7-F" SOD-123 -86.9,117.9 r0 top value=16V
D4 "KG DELLS1.22-JGKH-24" "FP-KG DELLS1.22-JGKH-24_0603-MFG" -90.3,99.9 r90 top
D7 "GB02SLT12-214" FP-GB02SLT12-214_DO-214AA-MFG -54.3,119.2 r0 top
D8 "BZT52C16-7-F" SOD-123 -62.35,116.25 r180 top value=16V
D10 "KG DELLS1.22-JGKH-24" "FP-KG DELLS1.22-JGKH-24_0603-MFG" -93.7,111.2 r90 top
D13 "B160-13-F" SMA -201.75,108.25 r0 top value=60V
D14 "1N4148W-7-F" SOD-123 -66.138,8.5 r180 top value=100V
D15 "ES1JAF" SMAF -68.25,3.75 r270 top value=600V
D16 "KG DELLS1.22-JGKH-24" "FP-KG DELLS1.22-JGKH-24_0603-MFG" -28.5,2.5 r180 top
D17 "KG DELLS1.22-JGKH-24" "FP-KG DELLS1.22-JGKH-24_0603-MFG" -148.7,79.5 r270 top
D18 "KG DELLS1.22-JGKH-24" "FP-KG DELLS1.22-JGKH-24_0603-MFG" -140.9,80.775 r90 top
D19 "BZT52C16-7-F" SOD-123 -45,24 r180 top value=16V
D20 "RS3K-E3/9AT" SMC -51,19.775 r90 top value=800V
D23 "KG DELLS1.22-JGKH-24" "FP-KG DELLS1.22-JGKH-24_0603-MFG" -165.5,76.2 r90 top
D24 "KG DELLS1.22-JGKH-24" "FP-KG DELLS1.22-JGKH-24_0603-MFG" -162.5,89.5 r180 top
D25 "KG DELLS1.22-JGKH-24" "FP-KG DELLS1.22-JGKH-24_0603-MFG" -117.4,90.3 r270 top
D26 "KG DELLS1.22-JGKH-24" "FP-KG DELLS1.22-JGKH-24_0603-MFG" -56.3,116.45 r0 top
D27 "KG DELLS1.22-JGKH-24" "FP-KG DELLS1.22-JGKH-24_0603-MFG" -57.75,102 r180 top
D28 "KG DELLS1.22-JGKH-24" "FP-KG DELLS1.22-JGKH-24_0603-MFG" -43.37,116.5 r180 top
F1 "SF-3812F2000T-2" FP-SF-3812F2000T-2_3812-MFG -259,141 r180 top
F2 "SF-3812F2000T-2" FP-SF-3812F2000T-2_3812-MFG -259,130 r180 top
FB1 "MH1608-601Y" FP-MH1608-601Y_0603-MFG -85.45,27.975 r0 top
FB2 "MH1608-601Y" FP-MH1608-601Y_0603-MFG -130.375,105.725 r90 top
FB3 "MH1608-601Y" FP-MH1608-601Y_0603-MFG -124.4,112.4 r90 top
FB4 "MH1608-601Y" FP-MH1608-601Y_0603-MFG -52.5,72.25 r180 top
FB5 "MH1608-601Y" FP-MH1608-601Y_0603-MFG -38.25,100.5 r270 top
FB6 "MH1608-601Y" FP-MH1608-601Y_0603-MFG -184.75,105.4 r180 top
FB7 "MH1608-601Y" FP-MH1608-601Y_0603-MFG -167.126,61.554 r180 top
FB8 "MH1608-601Y" FP-MH1608-601Y_0603-MFG -214.05,61.7 r0 top
FB9 "MH1608-601Y" FP-MH1608-601Y_0603-MFG -171.51,90.264 r180 top
FB11 "MH1608-601Y" FP-MH1608-601Y_0603-MFG -151.217,85.365 r90 top
FB12 "MH1608-601Y" FP-MH1608-601Y_0603-MFG -97,18 r0 top
FB13 "MH1608-601Y" FP-MH1608-601Y_0603-MFG -149.525,111.558 r0 top
FB14 "MH1608-601Y" FP-MH1608-601Y_0603-MFG -227.5,118.75 r0 top
FB15 "MH1608-601Y" FP-MH1608-601Y_0603-MFG -40,24.5 r90 top
FB18 "BLM15EX331SN1D" FP-BLM15EX331SN1D_0402-MFG -259.252,106.371 r180 top
FB23 "BLM15EX331SN1D" FP-BLM15EX331SN1D_0402-MFG -258.75,66.25 r90 top
FID1 "Fiducial" Fiducial10-20 -208.5,166.5 r0 top
FID2 "Fiducial" Fiducial10-20 -226.8,53.5 r0 top
FID3 "Fiducial" Fiducial10-20 -13,1.5 r0 top
FID4 "Fiducial" Fiducial10-20 -14.5,127 r180 bottom
FID5 "Fiducial" Fiducial10-20 -39.5,166.4 r180 bottom
FID6 "Fiducial" Fiducial10-20 -13,1.5 r180 bottom
J1 "796636-3" FP-796636-3_HDR3-MFG -270.325,135.67 r90 top
J2 "796636-3" FP-796636-3_HDR3-MFG -79.6,4.75 r180 top
J3 "796636-3" FP-796636-3_HDR3-MFG -180,165 r0 top
J6 "694106402002" FP-694106402002_CONN_PWR_10MM7_9MM0-MFG -108.7,56.3 r0 top
J7 "61300211121" WURTH_61300211121 -65.25,29 r270 top
J8 "SSM-107-L-SV-BE" FP-SSM-107-L-SV-BE_HDR7-MFG -153.9,64.503 r180 top
J10 "SHF-112-01-L-D-TH" FP-SHF-112-01-L-D-TH_HDR24-MFG -154,55 r180 top
J11 "HSEC8-160-01-L-DV-A-BL" controlCARD-120HSEC -199.45,84.676 r0 top
J12 "SHF-112-01-L-D-TH" FP-SHF-112-01-L-D-TH_HDR24-MFG -130,55 r180 top
J15 "618009231121" Wurth_618009231121 -274.919,99.608 r180 top
J16 "61300211121" WURTH_61300211121 -252.6,83.5 r0 top
J17 "618009231121" Wurth_618009231121 -275.025,67 r180 top
K1 "2071556-3" FP-2071556-3_PTH_RELAY_18MM2_10MM2-MFG -201.95,120.656 r270 top
K2 "2071556-3" FP-2071556-3_PTH_RELAY_18MM2_10MM2-MFG -198.7,159.1 r90 top
L1 "B180990" FP-B180990_PTH12_39MM8_41MM4-MFG -106.75,145 r90 top value=95.16uH
L2 "SDEM20161T-4R7MS" FP-SDEM20161T-4R7MS_SMD2-MFG -91.9,97.4 r270 top
L3 "SDEM20161T-4R7MS" FP-SDEM20161T-4R7MS_SMD2-MFG -91.45,111.6 r270 top
L4 "B180990" FP-B180990_PTH12_39MM8_41MM4-MFG -40.25,146 r90 top value=95.16uH
L5 "SDEM20161T-4R7MS" FP-SDEM20161T-4R7MS_SMD2-MFG -105.825,97.4 r270 top
L6 "SDEM20161T-4R7MS" FP-SDEM20161T-4R7MS_SMD2-MFG -56.1,112.1 r90 top
L7 "SDEM20161T-4R7MS" FP-SDEM20161T-4R7MS_SMD2-MFG -56.25,97.3 r90 top
L8 "BLM18HE152SN1D" 0603 -230.042,104.064 r180 top value="1500 ohm"
L9 "SDEM20161T-4R7MS" FP-SDEM20161T-4R7MS_SMD2-MFG -43,112.5 r0 top
L10 "D6744" FP-D6744_PTH_CMC_38MM0-MFG -148.7,137 r270 top
L11 "D6744" FP-D6744_PTH_CMC_38MM0-MFG -225.9,149.3 r90 top
L12 "BLM18HE152SN1D" 0603 -233.598,94.412 r180 top value="1500 ohm"
L13 "MSS1210-224KE" MSS1210 -41.4,6.9 r0 top value=220uH
L14 "SRN3015-100M" SRN3015 -162.766,73.881 r270 top value=10uH
L16 "BLM18HE152SN1D" 0603 -229.519,65.058 r180 top value="1500 ohm"
L17 "BLM18HE152SN1D" 0603 -235.08,55.042 r180 top value="1500 ohm"
L25 "ACT45B-101-2P-TL003" FP-ACT45B-101-2P-TL003_SMT_4MM5_3MM2-MFG -258.525,86 r270 top
L31 "ACT45B-101-2P-TL003" FP-ACT45B-101-2P-TL003_SMT_4MM5_3MM2-MFG -254.6,71.9 r180 top
LBL1 "THT-14-423-10" Label_650x200 -95.5,41.25 r90 top
LOGO1 "CAUTION HOT SURFACE" IEC_HotSurface_Small -62.75,120.75 r0 top
LOGO2 "DANGER HIGH VOLTAGE" IEC_HighVoltage_Small -18,3.25 r0 top
Logo3 "CE Mark" CE_Mark_5mm -97.75,59 r0 top
Logo5 "FCC disclaimer" FCC_disclaimer -50.675,54.65 r270 top
Logo6 "WEEE logo" WEEE_Minimum -96.25,68.5 r0 top
MP1 "9774015960R" FP-9774015960R_ROUND_SPACER_6MM0-MFG -270,165 r180 bottom
MP2 "9774015960R" FP-9774015960R_ROUND_SPACER_6MM0-MFG -137.5,165 r180 bottom
MP3 "9774015960R" FP-9774015960R_ROUND_SPACER_6MM0-MFG -80,132.25 r180 bottom
MP5 "9774015960R" FP-9774015960R_ROUND_SPACER_6MM0-MFG -5,5 r180 bottom
MP6 "9774015960R" FP-9774015960R_ROUND_SPACER_6MM0-MFG -5,125.825 r180 bottom
MP7 "9774015960R" FP-9774015960R_ROUND_SPACER_6MM0-MFG -5,85 r180 bottom
MP8 "9774015960R" FP-9774015960R_ROUND_SPACER_6MM0-MFG -102.1,74.45 r180 bottom
MP9 "9774015960R" FP-9774015960R_ROUND_SPACER_6MM0-MFG -5,165 r180 bottom
MP10 "9774015960R" FP-9774015960R_ROUND_SPACER_6MM0-MFG -95,5 r180 bottom
MP12 "9774015960R" FP-9774015960R_ROUND_SPACER_6MM0-MFG -242,86 r180 bottom
Q1 "CSD17318Q2" FP-CSD17318Q2_WSON6-MFG -200,104.25 r90 top
Q2 "STD3NK80ZT4" DPAK -60.25,20 r180 top value=800V
R1 "CSS2H-2512R-1L00F" CSS2H-2512_H077Y042 -71.5,25.5 r90 top value=0.001
R2 "RG1608P-560-B-T5" 0603 -82.5,24.6 r180 top value=56
R3 "RT0603BRD0710RL" 0603 -77.175,22.7 r180 top value=10.0
R4 "RT0603BRD0710RL" 0603 -77.2,28.725 r180 top value=10.0
R5 "RG1608P-103-B-T5" 0603 -238,111 r270 top value=10.0k
R6 "TMP6131LPGM" LPG0002A-MFG -240.29,114 r90 top value=10kΩ
R7 "CRCW12064R70JNEAHP" 1206 -98.75,92.175 r270 top value=4.7
R8 "RG1608P-560-B-T5" 0603 -112.875,121 r0 top value=56
R9 "RG1608P-560-B-T5" 0603 -112.875,119.6 r0 top value=56
R10 "RC0603FR-0720KL" 0603 -85.2,99.225 r270 top value=20.0k
R11 "ERJ-3EKF1202V" 0603 -126.725,110.3 r270 top value=12.0k
R12 "RT0603DRE0738K8L" 0603 -110.675,107.625 r90 top value=38.8k
R13 "ERJ-3EKF1202V" 0603 -132.175,106.025 r90 top value=12.0k
R14 "RC0603FR-073K01L" 0603 -133.875,106.025 r90 top value=3.01k
R15 "RG1608P-103-B-T5" 0603 -109.875,110.125 r180 top value=10.0k
R16 "CRCW06032K70JNEA" 0603 -165,97.5 r0 top value=2.7k
R17 "RC0603JR-075K6L" 0603 -91.8,100.2 r90 top value=5.6k
R18 "RG1608P-560-B-T5" 0603 -43.175,89.375 r180 top value=56
R19 "RG1608P-560-B-T5" 0603 -46.3,90.875 r180 top value=56
R20 "RG1608P-560-B-T5" 0603 -128.95,120.125 r0 top value=56
R21 "TNPV1206680KBEEN" TNPV1206 -85.5,12.5 r90 top value=680k
R22 "RG1608P-560-B-T5" 0603 -128.95,118.425 r0 top value=56
R23 "TNPV1206680KBEEN" TNPV1206 -83,15.5 r90 top value=680k
R24 "RG1608P-560-B-T5" 0603 -126.525,116.475 r0 top value=56
R25 "RG1608P-560-B-T5" 0603 -87,113.5 r270 top value=56
R26 "RG1608P-560-B-T5" 0603 -126.55,115.075 r0 top value=56
R27 "RG1608P-560-B-T5" 0603 -86.85,99.225 r270 top value=56
R28 "RG1608P-560-B-T5" 0603 -129.9,114.125 r0 top value=56
R29 "RG1608P-560-B-T5" 0603 -108.8,116.95 r90 top value=56
R30 "RC0603FR-0720KL" 0603 -85.25,113.525 r270 top value=20.0k
R31 "RG1608P-560-B-T5" 0603 -129.9,112.6 r0 top value=56
R32 "RG1608P-560-B-T5" 0603 -104.7,110 r90 top value=56
R33 "RG1608P-103-B-T5" 0603 -65.5,92.3 r0 top value=10.0k
R34 "RG1608P-103-B-T5" 0603 -65.5,87.9 r0 top value=10.0k
R35 "RG1608P-560-B-T5" 0603 -104.575,100.025 r270 top value=56
R36 "TNPV1206680KBEEN" TNPV1206 -83,20.1 r90 top value=680k
R37 "RG1608P-560-B-T5" 0603 -101.15,99.3 r270 top value=56
R38 "RG1608P-560-B-T5" 0603 -141.846,85.23 r180 top value=56
R39 "RG1608P-560-B-T5" 0603 -141.846,89.04 r0 top value=56
R40 "RC0603FR-0720KL" 0603 -99.4,99.3 r270 top value=20.0k
R41 "CRCW12064R70JNEAHP" 1206 -101.2,92.175 r270 top value=4.7
R42 "RC0603JR-075K6L" 0603 -92.1,113.6 r180 top value=5.6k
R43 "RC0603JR-075K6L" 0603 -117.4,87.6 r90 top value=5.6k
R44 "RC0603FR-0720KL" 0603 -62.1,110 r90 top value=20.0k
R45 "RT0603DRE0738K8L" 0603 -54.5,91.75 r180 top value=38.8k
R46 "ERJ-3EKF1202V" 0603 -52.5,70.5 r180 top value=12.0k
R47 "ERJ-3EKF1202V" 0603 -57,76.025 r0 top value=12.0k
R48 "RC0603FR-073K01L" 0603 -52.5,69 r180 top value=3.01k
R49 "RG1608P-103-B-T5" 0603 -57,92.5 r270 top value=10.0k
R50 "RG1608P-103-B-T5" 0603 -235.25,92 r0 top value=10.0k
R51 "RC0603JR-075K6L" 0603 -54.4,115.2 r90 top value=5.6k
R52 "RC0603JR-075K6L" 0603 -60.5,102 r0 top value=5.6k
R53 "CRCW12064R70JNEAHP" 1206 -48.3,116.475 r180 top value=4.7
R54 "RG1608P-560-B-T5" 0603 -37.7,87.5 r0 top value=56
R55 "CRCW12064R70JNEAHP" 1206 -48.275,118.975 r180 top value=4.7
R56 "RG1608P-560-B-T5" 0603 -37.8,84 r0 top value=56
R57 "RCS06030000Z0EA" 0603 -189.8,74.1 r90 top value=0
R58 "RG1608P-560-B-T5" 0603 -35.05,82.725 r90 top value=56
R59 "RG1608P-560-B-T5" 0603 -61.3,95.8 r90 top value=56
R60 "RC0603FR-0720KL" 0603 -63,95.825 r90 top value=20.0k
R61 "RG1608P-560-B-T5" 0603 -34.25,86 r90 top value=56
R62 "RG1608P-560-B-T5" 0603 -60.4,110 r90 top value=56
R63 "RG1608P-560-B-T5" 0603 -33.25,82.75 r90 top value=56
R64 "RG1608P-560-B-T5" 0603 -58.75,88.7 r270 top value=56
R65 "RG1608P-560-B-T5" 0603 -32,86 r90 top value=56
R66 "RG1608P-560-B-T5" 0603 -52.5,97.5 r180 top value=56
R67 "RG1608P-560-B-T5" 0603 -141.846,94.628 r180 top value=56
R68 "RG1608P-560-B-T5" 0603 -145.014,94.629 r90 top value=56
R69 "RG1608P-560-B-T5" 0603 -42.5,109.5 r180 top value=56
R70 "RC0603JR-07680RL" 0603 -167.2,75.9 r270 top value=680
R71 "RG1608P-560-B-T5" 0603 -46.9,109.875 r90 top value=56
R72 "RG1608P-560-B-T5" 0603 -156.287,95.365 r0 top value=56
R73 "RG1608P-560-B-T5" 0603 -151.875,93.8 r180 top value=56
R74 "RC0603FR-0720KL" 0603 -48.625,109.875 r90 top value=20.0k
R75 "PTCEL13R600LBE" FP-PTCEL13R600LBE_RADIAL-MFG -200.4,134.9 r0 top value=60Ω
R76 "RC0603JR-07680RL" 0603 -160.25,91 r180 top value=680
R77 "ERJ-8ENF1693V" 1206 -5.343,145.226 r0 top value=169k
R78 "IsoM5-275-B-L2" FP-IsoM5-275-B-L2_RADIAL-MFG -260,160.25 r270 top
R79 "ERJ-8ENF1693V" 1206 -5.269,142.273 r0 top value=169k
R80 "ERJ-8ENF1693V" 1206 -5.343,139.225 r0 top value=169k
R81 "IsoM5-275-B-L2" FP-IsoM5-275-B-L2_RADIAL-MFG -251,160 r270 top
R82 "IsoM5-275-B-L2" FP-IsoM5-275-B-L2_RADIAL-MFG -247,131 r90 top
R83 "RG1608P-560-B-T5" 0603 -189.156,110.165 r270 top value=56
R84 "RG1608P-103-B-T5" 0603 -194.978,110.279 r90 top value=10.0k
R85 "RG1608P-103-B-T5" 0603 -188.108,105.34 r180 top value=10.0k
R86 "RG1608P-560-B-T5" 0603 -191.095,110.203 r90 top value=56
R87 "RG1608P-560-B-T5" 0603 -187.25,110.175 r270 top value=56
R88 "RG1608P-560-B-T5" 0603 -193.039,110.279 r270 top value=56
R89 "RT0603DRE07200RL" 0603 -196.5,100.8 r90 top value=200
R90 "RG1608P-103-B-T5" 0603 -198.125,100.8 r270 top value=10.0k
R91 "RG1608P-103-B-T5" 0603 -180.896,108.373 r180 top value=10.0k
R92 "RT0603DRE075K76L" 0603 -180.896,110.151 r0 top value=5.76k
R93 "RT0603DRE0738K3L" 0603 -67,11.5 r90 top value=38.3k
R94 "CRCW1206475KFKEA" 1206 -65.25,3.15 r270 top value=475k
R95 "RT0603DRE0715K6L" 0603 -65,11.5 r270 top value=15.6k
R96 "RT0603DRE07301RL" 0603 -56.15,13 r270 top value=301
R97 "ERJ-6RQFR68V" 0805_HV -53,12.65 r0 top value=0.68
R98 "CSR1206FKR750" 1206 -53.65,10.025 r0 top value=0.75
R99 "RG1608P-103-B-T5" 0603 -254.2,100.75 r0 top value=10.0k
R100 "RC0603JR-075K6L" 0603 -26.5,5 r90 top value=5.6k
R101 "ERJ-3GEYJ152V" 0603 -146.9,79.8 r90 top value=1.5k
R102 "RC0603JR-07680RL" 0603 -142.783,80.538 r270 top value=680
R103 "RT0603BRD07105KL" 0603 -153.252,77.327 r270 top value=105k
R104 "RG1608P-103-B-T5" 0603 -158.625,78.7 r180 top value=10.0k
R105 "RG1608P-103-B-T5" 0603 -161.6,95 r90 top value=10.0k
R106 "RT0603DRE0720KL" 0603 -155.03,77.327 r90 top value=20.0k
R107 "CRCW06031K50JNEA" 0603 -162.397,78.597 r0 top value=1.5k
R108 "RG1608P-103-B-T5" 0603 -218.95,116.8 r90 top value=10.0k
R109 "RG1608P-103-B-T5" 0603 -222.4,107.975 r0 top value=10.0k
R110 "RG1608P-103-B-T5" 0603 -85.5,21.5 r270 top value=10.0k
R111 "TNPV12061M00BEEN" TNPV1206 -209.75,125.5 r270 top value=1.00Meg
R112 "TNPV12061M00BEEN" TNPV1206 -212.25,122.15 r270 top value=1.00Meg
R113 "TNPV12061M00BEEN" TNPV1206 -209.75,118.75 r270 top value=1.00Meg
R114 "PTCEL13R600LBE" FP-PTCEL13R600LBE_RADIAL-MFG -198.5,143.5 r0 top value=60Ω
R115 "RC0603JR-075K6L" 0603 -44.5,118.9 r270 top value=5.6k
R116 "TNPV12061M00BEEN" TNPV1206 -175.15,120.8 r270 top value=1.00Meg
R117 "TNPV12061M00BEEN" TNPV1206 -177.5,117.5 r270 top value=1.00Meg
R118 "TNPV12061M00BEEN" TNPV1206 -175.108,114.006 r270 top value=1.00Meg
R120 "RG1608P-560-B-T5" 0603 -219,112 r0 top value=56
R121 "RG1608P-560-B-T5" 0603 -226.25,103.5 r270 top value=56
R122 "TNPV12061M00BEEN" TNPV1206 -219.75,127.5 r270 top value=1.00Meg
R123 "TNPV12061M00BEEN" TNPV1206 -217.25,124.25 r270 top value=1.00Meg
R124 "TNPV12061M00BEEN" TNPV1206 -219.75,121 r270 top value=1.00Meg
R125 "RG1608P-103-B-T5" 0603 -232.5,62.75 r0 top value=10.0k
R126 "RG1608P-103-B-T5" 0603 -253.448,63.698 r0 top value=10.0k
